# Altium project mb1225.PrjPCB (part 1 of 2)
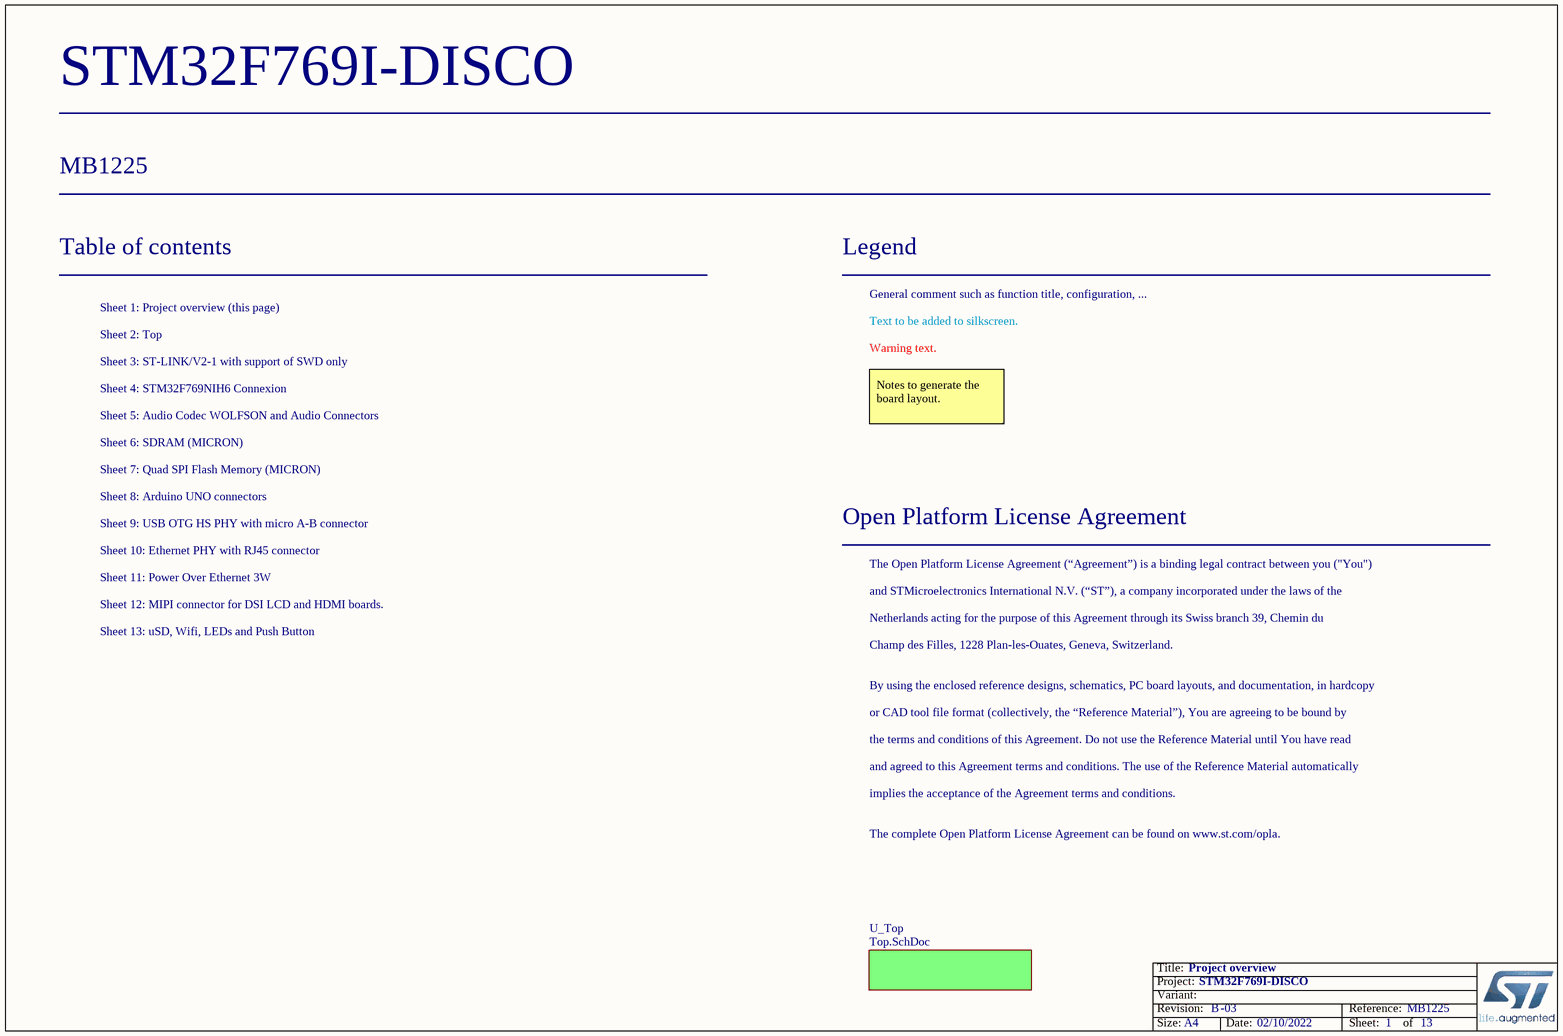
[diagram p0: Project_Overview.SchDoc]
Board_Reference: MB1225; Board_PCB_Revision: B; Board_Name: STM32F769I-DISCO; Board_document_Date: 02/10/2022; Board_Assembly_Revision: 03
13 sheets, 456 parts. Net scope: flat (ports and power ports of the same name join across sheets).
Board file: MB1225.PcbDoc
Sheets:
  Project_Overview.SchDoc
    U_Top = TOP.SchDoc
      U_ST_LINK_V2-1 = ST_LINK_V2-1.SCHDOC
      U_AUDIO = AUDIO.SchDoc
      U_Peripherals = Peripherals.SchDoc
      U_QSPI = QSPI.SchDoc
      U_Arduino_ Connectors = Arduino_ Connectors.SchDoc
      U_SDRAM = SDRAM.SchDoc
      U_USB_OTG_HS = USB_OTG_HS.SchDoc
      U_STM32F7 = STM32F7.SchDoc
      U_Ethernet = Ethernet.SchDoc
        U_PoE = PoE.SchDoc
      U_DSI_LCD = DSI_LCD.SchDoc

## Sheet Project_Overview.SchDoc: Project overview
size A4; Date: Not used; ApprovedBy: Not used; CheckedBy: Not used; Author: Not used; CompanyName: STMicroelectronics; DrawnBy: Not used; Engineer: Not used; Organization: Not used; Address1: Not used; Address2: Not used; Address3: Not used; Address4: Not used; DocumentNumber: Not used; Revision: Not used; SheetNumber: 1; SheetTotal: 13

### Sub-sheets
U_Top = Top.SchDoc: no entries

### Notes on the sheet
- Table of contents
- Sheet 1: Project overview (this page)
- Legend
- General comment such as function title, configuration, ...
- Sheet 2: Top
- Sheet 3: ST-LINK/V2-1 with support of SWD only
- Text to be added to silkscreen.
- Warning text.
- Sheet 4: STM32F769NIH6 Connexion
- Sheet 6: SDRAM (MICRON)
- Sheet 5: Audio Codec WOLFSON and Audio Connectors
- Notes to generate the board layout.
- Sheet 7: Quad SPI Flash Memory (MICRON)
- Sheet 8: Arduino UNO connectors
- Sheet 9: USB OTG HS PHY with micro A-B connector
- Sheet 10: Ethernet PHY with RJ45 connector
- Sheet 11: Power Over Ethernet 3W
- Open Platform License Agreement
- The Open Platform License Agreement (“Agreement”) is a binding legal contract between you ("You")
- Sheet 12: MIPI connector for DSI LCD and HDMI boards.
- Sheet 13: uSD, Wifi, LEDs and Push Button
- and STMicroelectronics International N.V. (“ST”), a company incorporated under the laws of the
- Netherlands acting for the purpose of this Agreement through its Swiss branch 39, Chemin du
- Champ des Filles, 1228 Plan-les-Ouates, Geneva, Switzerland.
- By using the enclosed reference designs, schematics, PC board layouts, and documentation, in hardcopy
- or CAD tool file format (collectively, the “Reference Material”), You are agreeing to be bound by
- the terms and conditions of this Agreement. Do not use the Reference Material until You have read
- and agreed to this Agreement terms and conditions. The use of the Reference Material automatically
- implies the acceptance of the Agreement terms and conditions.
- The complete Open Platform License Agreement can be found on www.st.com/opla.

## Sheet TOP.SchDoc: STM32F769 Discovery Interconnexion
size A4; Date: 29-OCT-2015; Author: A.B; CompanyName: STMicroelectronics; Organization: MCD/TOOLS/GNB; Address1: 12, Rue Jules HOROWITZ; Address2: 38019 Grenoble; Address3: FRANCE; DocumentNumber: MB1225; Revision: B-01; SheetNumber: 2; SheetTotal: 13; Project: STM32F769I-DISCO
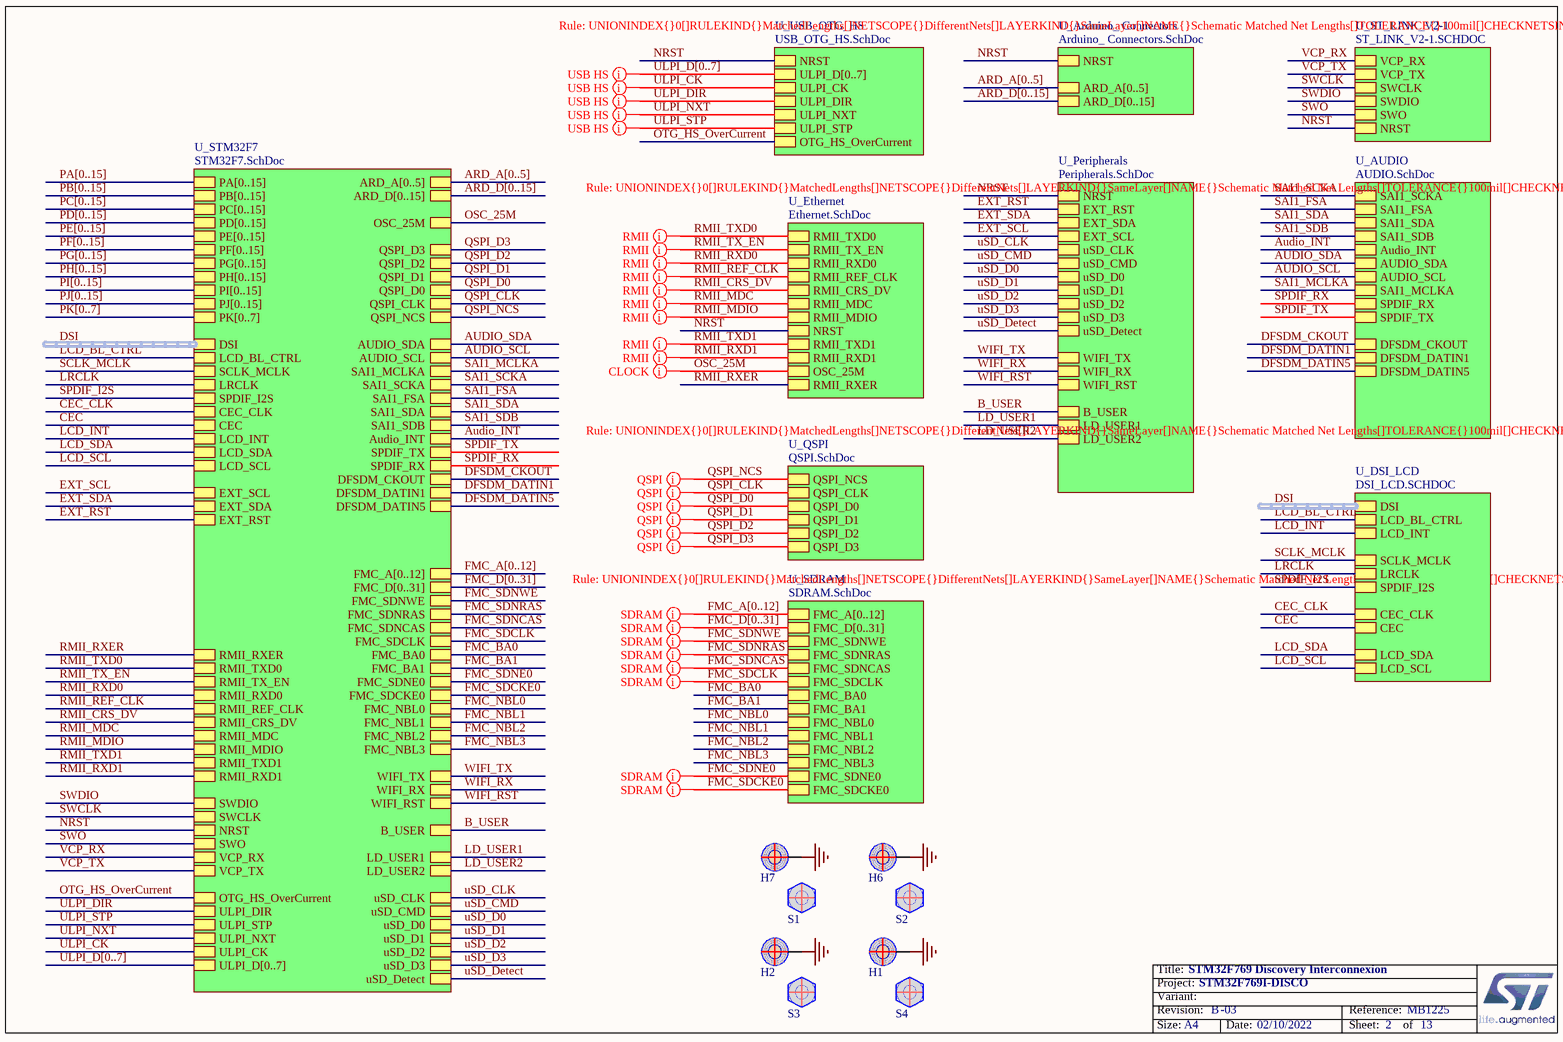
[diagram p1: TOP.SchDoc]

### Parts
H1  POSITION HOLE C6D3R5  [HOLE_C6D3R5]  (value not drawn)
H2  POSITION HOLE C6D3R5  [HOLE_C6D3R5]  (value not drawn)
H6  POSITION HOLE C6D3R5  [HOLE_C6D3R5]  (value not drawn)
H7  POSITION HOLE C6D3R5  [HOLE_C6D3R5]  (value not drawn)
S1  Nylon Screw/Spacer M3x12.7  (value not drawn)
S2  Nylon Screw/Spacer M3x12.7  (value not drawn)
S3  Nylon Screw/Spacer M3x12.7  (value not drawn)
S4  Nylon Screw/Spacer M3x12.7  (value not drawn)

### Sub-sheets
U_Arduino_ Connectors = Arduino_ Connectors.SchDoc: NRST, ARD_D[0..15], ARD_A[0..5]
U_AUDIO = AUDIO.SchDoc: AUDIO_SDA, AUDIO_SCL, SAI1_MCLKA, SPDIF_RX, SAI1_SCKA, SAI1_FSA, SAI1_SDA, SAI1_SDB, Audio_INT, SPDIF_TX, DFSDM_CKOUT, DFSDM_DATIN1, DFSDM_DATIN5
U_DSI_LCD = DSI_LCD.SCHDOC: DSI (harness DSI), LCD_INT, LCD_BL_CTRL, SCLK_MCLK, LRCLK, SPDIF_I2S, CEC_CLK, CEC, LCD_SDA, LCD_SCL
U_Ethernet = Ethernet.SchDoc: RMII_TXD0, RMII_TX_EN, RMII_RXD0, RMII_REF_CLK, RMII_CRS_DV, RMII_MDC, RMII_MDIO, NRST, RMII_TXD1, RMII_RXD1, OSC_25M, RMII_RXER
U_Peripherals = Peripherals.SchDoc: NRST, EXT_RST, EXT_SCL, EXT_SDA, uSD_CLK, uSD_CMD, uSD_D0, uSD_D1, uSD_D2, uSD_D3, uSD_Detect, B_USER, WIFI_TX, WIFI_RX, WIFI_RST, LD_USER1, LD_USER2
U_QSPI = QSPI.SchDoc: QSPI_D0, QSPI_D3, QSPI_D1, QSPI_CLK, QSPI_NCS, QSPI_D2
U_SDRAM = SDRAM.SchDoc: FMC_A[0..12], FMC_SDNWE, FMC_SDNRAS, FMC_SDNCAS, FMC_SDCLK, FMC_BA0, FMC_BA1, FMC_NBL0, FMC_NBL1, FMC_SDNE0, FMC_SDCKE0, FMC_D[0..31], FMC_NBL2, FMC_NBL3
U_ST_LINK_V2-1 = ST_LINK_V2-1.SCHDOC: SWDIO, SWCLK, NRST, VCP_RX, VCP_TX, SWO
U_STM32F7 = STM32F7.SchDoc: PA[0..15], PB[0..15], PC[0..15], PD[0..15], PE[0..15], PF[0..15], PG[0..15], PH[0..15], PI[0..15], PJ[0..15], PK[0..7], OSC_25M, RMII_TXD0, RMII_TX_EN, RMII_RXD0, RMII_REF_CLK, RMII_CRS_DV, RMII_MDC, RMII_MDIO, RMII_TXD1, RMII_RXD1, ULPI_D[0..7], ULPI_CK, ULPI_DIR, ULPI_NXT, ULPI_STP, QSPI_D0, QSPI_D3, QSPI_D1, QSPI_CLK, QSPI_NCS, AUDIO_SDA, AUDIO_SCL, SAI1_MCLKA, EXT_SCL, EXT_SDA, EXT_RST, uSD_CLK, uSD_CMD, uSD_D0, uSD_D1, uSD_D2, uSD_D3, uSD_Detect, SWDIO, SWCLK, NRST, SWO, VCP_RX, VCP_TX, FMC_A[0..12], FMC_D[0..31], FMC_SDNWE, FMC_SDNRAS, FMC_SDNCAS, FMC_SDCLK, FMC_BA0, FMC_BA1, FMC_SDNE0, FMC_SDCKE0, FMC_NBL0, FMC_NBL1, SPDIF_RX, QSPI_D2, B_USER, ARD_D[0..15], RMII_RXER, OTG_HS_OverCurrent, SAI1_SCKA, SAI1_FSA, SAI1_SDA, SAI1_SDB, Audio_INT, SPDIF_TX, FMC_NBL2, FMC_NBL3, DSI (harness DSI), LCD_BL_CTRL, SCLK_MCLK, LRCLK, SPDIF_I2S, CEC_CLK, CEC, LCD_INT, LCD_SDA, LCD_SCL, WIFI_RST, WIFI_RX, WIFI_TX, ARD_A[0..5], LD_USER1, LD_USER2, DFSDM_CKOUT, DFSDM_DATIN1, DFSDM_DATIN5
U_USB_OTG_HS = USB_OTG_HS.SchDoc: ULPI_D[0..7], ULPI_CK, ULPI_DIR, ULPI_NXT, ULPI_STP, NRST, OTG_HS_OverCurrent

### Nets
GND: H1.1 H2.1 H6.1 H7.1  [project net POE7]
Audio_INT: sheet U_AUDIO/Audio_INT, sheet U_STM32F7/Audio_INT
AUDIO_SCL: sheet U_AUDIO/AUDIO_SCL, sheet U_STM32F7/AUDIO_SCL
AUDIO_SDA: sheet U_AUDIO/AUDIO_SDA, sheet U_STM32F7/AUDIO_SDA
B_USER: sheet U_Peripherals/B_USER, sheet U_STM32F7/B_USER
CEC: sheet U_STM32F7/CEC, sheet U_DSI_LCD/CEC
CEC_CLK: sheet U_STM32F7/CEC_CLK, sheet U_DSI_LCD/CEC_CLK
DFSDM_CKOUT: sheet U_AUDIO/DFSDM_CKOUT, sheet U_STM32F7/DFSDM_CKOUT
DFSDM_DATIN1: sheet U_AUDIO/DFSDM_DATIN1, sheet U_STM32F7/DFSDM_DATIN1
DFSDM_DATIN5: sheet U_AUDIO/DFSDM_DATIN5, sheet U_STM32F7/DFSDM_DATIN5
EXT_RST: sheet U_Peripherals/EXT_RST, sheet U_STM32F7/EXT_RST
EXT_SCL: sheet U_Peripherals/EXT_SCL, sheet U_STM32F7/EXT_SCL
EXT_SDA: sheet U_Peripherals/EXT_SDA, sheet U_STM32F7/EXT_SDA
FMC_BA0: sheet U_SDRAM/FMC_BA0, sheet U_STM32F7/FMC_BA0
FMC_BA1: sheet U_SDRAM/FMC_BA1, sheet U_STM32F7/FMC_BA1
FMC_NBL0: sheet U_SDRAM/FMC_NBL0, sheet U_STM32F7/FMC_NBL0
FMC_NBL1: sheet U_SDRAM/FMC_NBL1, sheet U_STM32F7/FMC_NBL1
FMC_NBL2: sheet U_SDRAM/FMC_NBL2, sheet U_STM32F7/FMC_NBL2
FMC_NBL3: sheet U_SDRAM/FMC_NBL3, sheet U_STM32F7/FMC_NBL3
FMC_SDCKE0: sheet U_SDRAM/FMC_SDCKE0, sheet U_STM32F7/FMC_SDCKE0
FMC_SDCLK: sheet U_SDRAM/FMC_SDCLK, sheet U_STM32F7/FMC_SDCLK
FMC_SDNCAS: sheet U_SDRAM/FMC_SDNCAS, sheet U_STM32F7/FMC_SDNCAS
FMC_SDNE0: sheet U_SDRAM/FMC_SDNE0, sheet U_STM32F7/FMC_SDNE0
FMC_SDNRAS: sheet U_SDRAM/FMC_SDNRAS, sheet U_STM32F7/FMC_SDNRAS
FMC_SDNWE: sheet U_SDRAM/FMC_SDNWE, sheet U_STM32F7/FMC_SDNWE
LCD_BL_CTRL: sheet U_STM32F7/LCD_BL_CTRL, sheet U_DSI_LCD/LCD_BL_CTRL
LCD_INT: sheet U_STM32F7/LCD_INT, sheet U_DSI_LCD/LCD_INT
LCD_SCL: sheet U_STM32F7/LCD_SCL, sheet U_DSI_LCD/LCD_SCL
LCD_SDA: sheet U_STM32F7/LCD_SDA, sheet U_DSI_LCD/LCD_SDA
LD_USER1: sheet U_Peripherals/LD_USER1, sheet U_STM32F7/LD_USER1
LD_USER2: sheet U_Peripherals/LD_USER2, sheet U_STM32F7/LD_USER2
LRCLK: sheet U_STM32F7/LRCLK, sheet U_DSI_LCD/LRCLK
NRST: sheet U_ST_LINK_V2-1/NRST, sheet U_Peripherals/NRST, sheet U_Arduino_ Connectors/NRST, sheet U_USB_OTG_HS/NRST, sheet U_STM32F7/NRST, sheet U_Ethernet/NRST
OSC_25M: sheet U_STM32F7/OSC_25M, sheet U_Ethernet/OSC_25M
OTG_HS_OverCurrent: sheet U_USB_OTG_HS/OTG_HS_OverCurrent, sheet U_STM32F7/OTG_HS_OverCurrent
QSPI_CLK: sheet U_QSPI/QSPI_CLK, sheet U_STM32F7/QSPI_CLK
QSPI_D0: sheet U_QSPI/QSPI_D0, sheet U_STM32F7/QSPI_D0
QSPI_D1: sheet U_QSPI/QSPI_D1, sheet U_STM32F7/QSPI_D1
QSPI_D2: sheet U_QSPI/QSPI_D2, sheet U_STM32F7/QSPI_D2
QSPI_D3: sheet U_QSPI/QSPI_D3, sheet U_STM32F7/QSPI_D3
QSPI_NCS: sheet U_QSPI/QSPI_NCS, sheet U_STM32F7/QSPI_NCS
RMII_CRS_DV: sheet U_STM32F7/RMII_CRS_DV, sheet U_Ethernet/RMII_CRS_DV
RMII_MDC: sheet U_STM32F7/RMII_MDC, sheet U_Ethernet/RMII_MDC
RMII_MDIO: sheet U_STM32F7/RMII_MDIO, sheet U_Ethernet/RMII_MDIO
RMII_REF_CLK: sheet U_STM32F7/RMII_REF_CLK, sheet U_Ethernet/RMII_REF_CLK
RMII_RXD0: sheet U_STM32F7/RMII_RXD0, sheet U_Ethernet/RMII_RXD0
RMII_RXD1: sheet U_STM32F7/RMII_RXD1, sheet U_Ethernet/RMII_RXD1
RMII_RXER: sheet U_STM32F7/RMII_RXER, sheet U_Ethernet/RMII_RXER
RMII_TX_EN: sheet U_STM32F7/RMII_TX_EN, sheet U_Ethernet/RMII_TX_EN
RMII_TXD0: sheet U_STM32F7/RMII_TXD0, sheet U_Ethernet/RMII_TXD0
RMII_TXD1: sheet U_STM32F7/RMII_TXD1, sheet U_Ethernet/RMII_TXD1
SAI1_FSA: sheet U_AUDIO/SAI1_FSA, sheet U_STM32F7/SAI1_FSA
SAI1_MCLKA: sheet U_AUDIO/SAI1_MCLKA, sheet U_STM32F7/SAI1_MCLKA
SAI1_SCKA: sheet U_AUDIO/SAI1_SCKA, sheet U_STM32F7/SAI1_SCKA
SAI1_SDA: sheet U_AUDIO/SAI1_SDA, sheet U_STM32F7/SAI1_SDA
SAI1_SDB: sheet U_AUDIO/SAI1_SDB, sheet U_STM32F7/SAI1_SDB
SCLK_MCLK: sheet U_STM32F7/SCLK_MCLK, sheet U_DSI_LCD/SCLK_MCLK
SPDIF_I2S: sheet U_STM32F7/SPDIF_I2S, sheet U_DSI_LCD/SPDIF_I2S
SPDIF_RX: sheet U_AUDIO/SPDIF_RX, sheet U_STM32F7/SPDIF_RX
SPDIF_TX: sheet U_AUDIO/SPDIF_TX, sheet U_STM32F7/SPDIF_TX
SWCLK: sheet U_ST_LINK_V2-1/SWCLK, sheet U_STM32F7/SWCLK
SWDIO: sheet U_ST_LINK_V2-1/SWDIO, sheet U_STM32F7/SWDIO
SWO: sheet U_ST_LINK_V2-1/SWO, sheet U_STM32F7/SWO
ULPI_CK: sheet U_USB_OTG_HS/ULPI_CK, sheet U_STM32F7/ULPI_CK
ULPI_DIR: sheet U_USB_OTG_HS/ULPI_DIR, sheet U_STM32F7/ULPI_DIR
ULPI_NXT: sheet U_USB_OTG_HS/ULPI_NXT, sheet U_STM32F7/ULPI_NXT
ULPI_STP: sheet U_USB_OTG_HS/ULPI_STP, sheet U_STM32F7/ULPI_STP
uSD_CLK: sheet U_Peripherals/uSD_CLK, sheet U_STM32F7/uSD_CLK
uSD_CMD: sheet U_Peripherals/uSD_CMD, sheet U_STM32F7/uSD_CMD
uSD_D0: sheet U_Peripherals/uSD_D0, sheet U_STM32F7/uSD_D0
uSD_D1: sheet U_Peripherals/uSD_D1, sheet U_STM32F7/uSD_D1
uSD_D2: sheet U_Peripherals/uSD_D2, sheet U_STM32F7/uSD_D2
uSD_D3: sheet U_Peripherals/uSD_D3, sheet U_STM32F7/uSD_D3
uSD_Detect: sheet U_Peripherals/uSD_Detect, sheet U_STM32F7/uSD_Detect
VCP_RX: sheet U_ST_LINK_V2-1/VCP_RX, sheet U_STM32F7/VCP_RX
VCP_TX: sheet U_ST_LINK_V2-1/VCP_TX, sheet U_STM32F7/VCP_TX
WIFI_RST: sheet U_Peripherals/WIFI_RST, sheet U_STM32F7/WIFI_RST
WIFI_RX: sheet U_Peripherals/WIFI_RX, sheet U_STM32F7/WIFI_RX
WIFI_TX: sheet U_Peripherals/WIFI_TX, sheet U_STM32F7/WIFI_TX

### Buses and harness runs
bus ARD_A[0..5] = sheet U_Arduino_ Connectors/ARD_A[0..5]
bus ARD_A[0..5] = sheet U_STM32F7/ARD_A[0..5]
bus ARD_D[0..15] = sheet U_Arduino_ Connectors/ARD_D[0..15]
bus ARD_D[0..15] = sheet U_STM32F7/ARD_D[0..15]
bus FMC_A[0..12] = sheet U_SDRAM/FMC_A[0..12]
bus FMC_A[0..12] = sheet U_STM32F7/FMC_A[0..12]
bus FMC_D[0..31] = sheet U_SDRAM/FMC_D[0..31]
bus FMC_D[0..31] = sheet U_STM32F7/FMC_D[0..31]
bus PA[0..15] = sheet U_STM32F7/PA[0..15]
bus PB[0..15] = sheet U_STM32F7/PB[0..15]
bus PC[0..15] = sheet U_STM32F7/PC[0..15]
bus PD[0..15] = sheet U_STM32F7/PD[0..15]
bus PE[0..15] = sheet U_STM32F7/PE[0..15]
bus PF[0..15] = sheet U_STM32F7/PF[0..15]
bus PG[0..15] = sheet U_STM32F7/PG[0..15]
bus PH[0..15] = sheet U_STM32F7/PH[0..15]
bus PI[0..15] = sheet U_STM32F7/PI[0..15]
bus PJ[0..15] = sheet U_STM32F7/PJ[0..15]
bus PK[0..7] = sheet U_STM32F7/PK[0..7]
bus ULPI_D[0..7] = sheet U_STM32F7/ULPI_D[0..7]
bus ULPI_D[0..7] = sheet U_USB_OTG_HS/ULPI_D[0..7]
harness DSI = sheet U_DSI_LCD/DSI
harness DSI = sheet U_STM32F7/DSI

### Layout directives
rule Matched Net Lengths [Tolerance = 100mil]: (no net found under the mark), FMC_SDCKE0, FMC_SDCLK, FMC_SDNCAS, FMC_SDNE0, FMC_SDNRAS, FMC_SDNWE, QSPI_CLK, QSPI_D0, QSPI_D1, QSPI_D2, QSPI_D3, QSPI_NCS, RMII_CRS_DV, RMII_MDC, RMII_MDIO, RMII_REF_CLK, RMII_RXD0, RMII_RXD1, RMII_TX_EN, RMII_TXD0, RMII_TXD1, ULPI_CK, ULPI_DIR, ULPI_NXT, ULPI_STP
rule Undefined: OSC_25M

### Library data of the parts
S1-S4 = Nylon_ScrewM3_Spacer_12.7: Nylon Screw M3 and Spacer 12.7; Manuf_Part_1: Screw M3x6 / Spacer M3x12.7; Manuf_1: JIUBABA; Provided: Sub Co

## Sheet ST_LINK_V2-1.SCHDOC: ST-LINK/V2-1 with support of SWD only
size A4; Date: 29-OCT-2015; Author: A.B; CompanyName: STMicroelectronics; Organization: MCD/TOOLS/GNB; Address1: 12, Rue Jules HOROWITZ; Address2: 38019 Grenoble; Address3: FRANCE; DocumentNumber: MB1225; Revision: B-01; SheetNumber: 3; SheetTotal: 13; Project: STM32F769I-DISCO
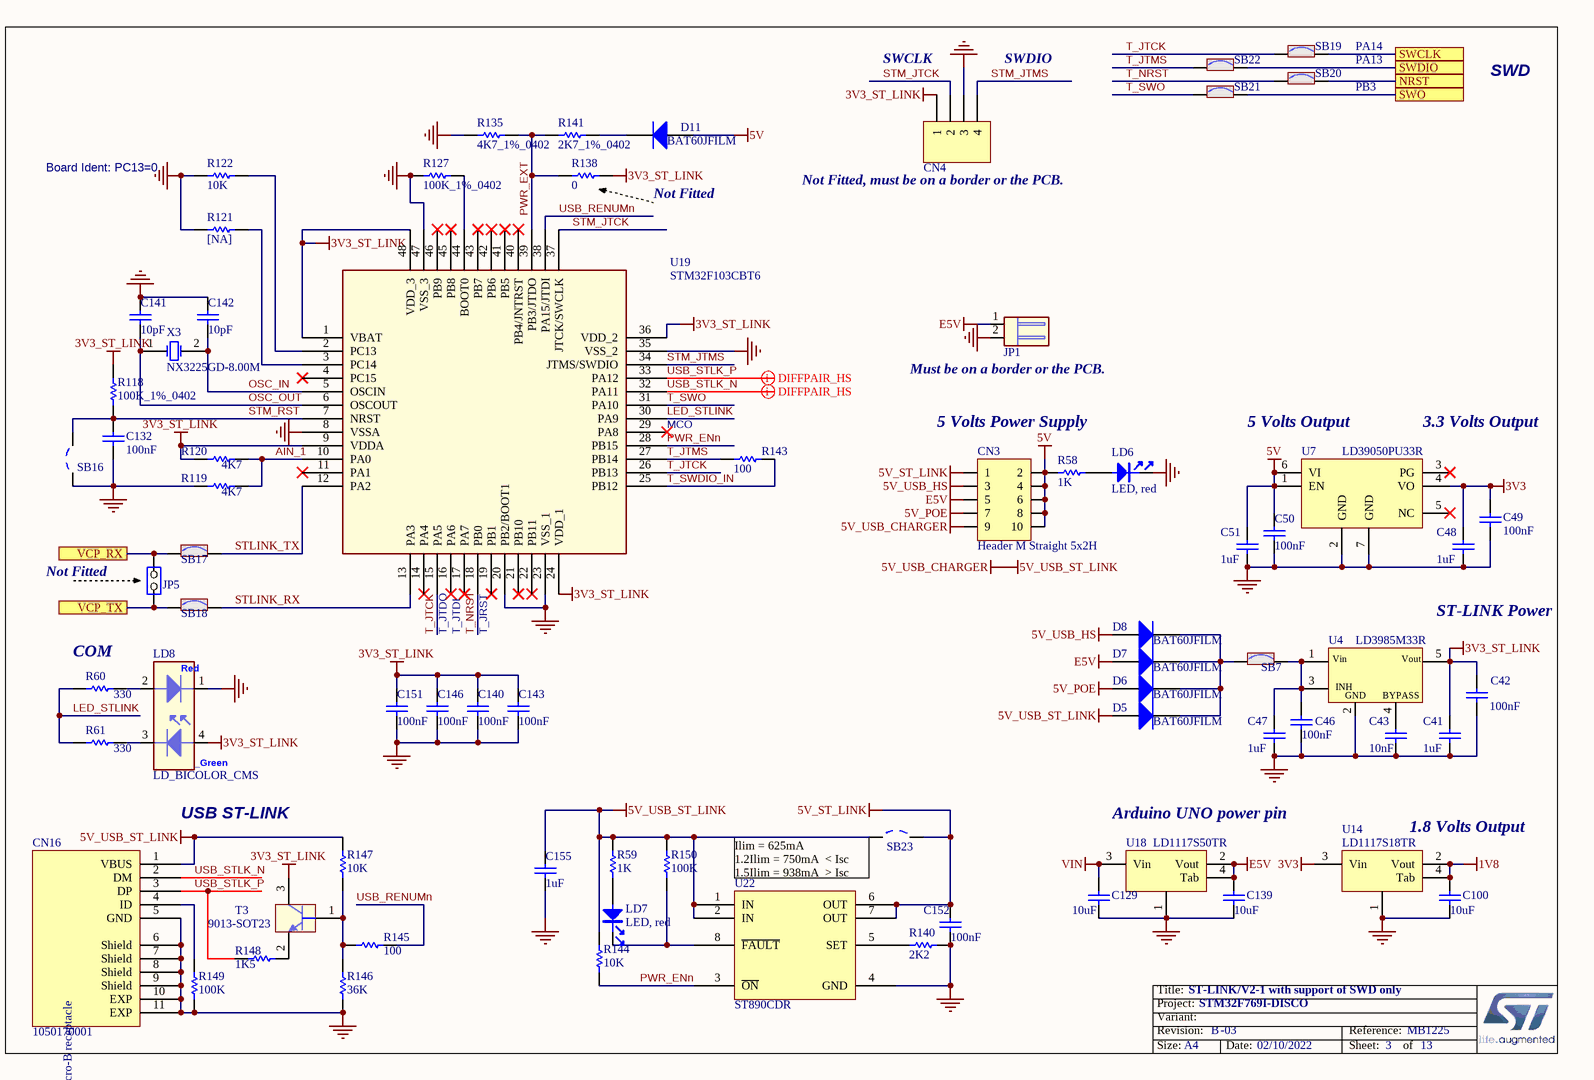
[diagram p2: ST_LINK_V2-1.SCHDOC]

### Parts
C41  1uF  [0603C]
C42  100nF  [0402C]
C43  10nF  [0603C]
C46  100nF  [0402C]
C47  1uF  [0603C]
C48  1uF  [0603C]
C49  100nF  [0402C]
C50  100nF  [0402C]
C51  1uF  [0603C]
C100  10uF  [0603C]
C129  10uF  [0805C]
C132  100nF  [0402C]
C139  10uF  [0805C]
C140  100nF  [0402C]
C141  10pF  [0402C]
C142  10pF  [0402C]
C143  100nF  [0402C]
C146  100nF  [0402C]
C151  100nF  [0402C]
C152  100nF  [0402C]
C155  1uF  [0603C]
CN3  Header M Straight 5x2H  [HDR_2X5_2R54]
CN4  Header 4  [HDR_1X4_2R54]  (value not drawn)
CN16  1050170001  [MICRO_USB_B_105017]
D5  BAT60JFILM  [SOD-323]
D6  BAT60JFILM  [SOD-323]
D7  BAT60JFILM  [SOD-323]
D8  BAT60JFILM  [SOD-323]
D11  BAT60JFILM  [SOD-323]
JP1  WF25402-06421  [HDR_1X2_2R54_RA_11R35]  (value not drawn)
JP5  JP2  [SIP2]  (value not drawn)
LD6  LED, red  [0603D]
LD7  LED, red  [0603D]
LD8  LD_BICOLOR_CMS  [LED2_3528]
R58  1K  [0402R]
R59  1K  [0402R]
R60  330  [0402R]
R61  330  [0402R]
R118  100K_1%_0402  [0402R]
R119  4K7  [0402R]
R120  4K7  [0402R]
R121  [NA]  [0402R]
R122  10K  [0402R]
R127  100K_1%_0402  [0402R]
R135  4K7_1%_0402  [0402R]
R138  0  [0402R]
R140  2K2  [0402R]
R141  2K7_1%_0402  [0402R]
R143  100  [0402R]
R144  10K  [0402R]
R145  100  [0402R]
R146  36K  [0402R]
R147  10K  [0402R]
R148  1K5  [0402R]
R149  100K  [0402R]
R150  100K  [0402R]
SB7  Solder Bridge ON  [JP2_SMD]  (value not drawn)
SB16  Solder Bridge OFF  [JP2_SMD]  (value not drawn)
SB17  Solder Bridge ON  [JP2_SMD]  (value not drawn)
SB18  Solder Bridge ON  [JP2_SMD]  (value not drawn)
SB19  Solder Bridge ON  [JP2_SMD]  (value not drawn)
SB20  Solder Bridge ON  [JP2_SMD]  (value not drawn)
SB21  Solder Bridge ON  [JP2_SMD]  (value not drawn)
SB22  Solder Bridge ON  [JP2_SMD]  (value not drawn)
SB23  Solder Bridge OFF  [JP2_SMD]  (value not drawn)
T3  9013-SOT23  [SOT-23]
U4  LD3985M33R  [SOT-23-5L]
U7  LD39050PU33R  [DFN6_0R95_3X3]
U14  LD1117S18TR  [SOT-223]
U18  LD1117S50TR  [SOT-223]
U19  STM32F103CBT6  [LQFP48_0R5_9X9]
U22  ST890CDR  [SOIC8_1R27_4R9X6]
X3  NX3225GD-8.00M  [XTAL_2SM_3R2X2R5_H1]

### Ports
NRST, SWCLK, SWDIO, SWO, VCP_RX, VCP_TX

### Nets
1V8: C100.2 U14.2(Vout) U14.4(Tab)
3V3: C48.2 C49.2 U7.4(VO) U14.3(Vin)
3V3_ST_LINK: C41.1 C42.2 C140.1 C143.2 C146.2 C151.2 CN4.1 LD8.4 R118.2 R120.1 R138.2 T3.3(C) U4.5(Vout) U19.1(VBAT) U19.9(VDDA) U19.24(VDD_1) U19.36(VDD_2) U19.48(VDD_3)
5V: C50.2 C51.2 CN3.2 CN3.4 CN3.6 CN3.8 CN3.10 D11.1(A) R58.1 U7.1(EN) U7.6(VI)
5V_POE: CN3.7 D6.1(A)
5V_ST_LINK: C152.2 CN3.1 SB23.2 U22.6(OUT) U22.7(OUT)
5V_USB_CHARGER: C155.2 CN3.9 CN16.1(VBUS) D5.1(A) R59.2 R144.2 R147.2 R150.2 SB23.1 U22.1(IN) U22.2(IN)  [also labelled 5V_USB_ST_LINK]
5V_USB_HS: CN3.3 D8.1(A)
E5V: C139.2 CN3.5 D7.1(A) JP1.1 U18.2(Vout) U18.4(Tab)
GND: C41.2 C42.1 C43.1 C46.1 C47.1 C48.1 C49.1 C50.1 C51.1 C100.1 C129.1 C132.1 C139.1 C140.2 C141.1 C142.1 C143.1 C146.1 C151.1 C152.1 C155.1 CN4.3 CN16.5(GND) CN16.6(Shield) CN16.7(Shield) CN16.8(Shield) CN16.9(Shield) CN16.10(EXP) CN16.11(EXP) JP1.2 LD6.2 LD8.1 R119.1 R121.1 R122.1 R127.1 R135.1 R140.2 R146.1 R149.1 SB16.1 U4.2(GND) U7.2(GND) U7.7(GND) U14.1 U18.1 U19.8(VSSA) U19.20(PB2/BOOT1) U19.23(VSS_1) U19.35(VSS_2) U19.47(VSS_3) U22.4(GND)  [project net POE7]
VIN: C129.2 U18.3(Vin)
AIN_1: R119.2 R120.2 U19.10(PA0)
LED_STLINK: R60.1 R61.1 U19.30(PA9)
NRST: SB20.2 ; port NRST
OSC_IN: C142.2 U19.5(OSCIN) X3.2(OSC2)
OSC_OUT: C141.2 U19.6(OSCOUT) X3.1(OSC1)
PA9: JP5.1(COMMON) SB18.1 ; port VCP_TX
PA10: JP5.2(NO) SB17.1 ; port VCP_RX
PA13: SB22.2 ; port SWDIO
PA14: SB19.2 ; port SWCLK
PWR_ENn: R144.1 U19.28(PB15) U22.3(~{ON})
PWR_EXT: R135.2 R138.1 R141.1 U19.39(PB3/JTDO)
STLINK_RX: SB18.2 U19.13(PA3)
STLINK_TX: SB17.2 U19.12(PA2)
STM_JTCK: CN4.2 U19.37(JTCK/SWCLK)
STM_JTMS: CN4.4 U19.34(JTMS/SWDIO)
STM_RST: C132.2 R118.1 SB16.2 U19.7(NRST)
SWO: SB21.2 ; port SWO
T_JTCK: SB19.1 U19.15(PA5) U19.26(PB13)
T_JTMS: R143.1 SB22.1 U19.27(PB14)
T_NRST: SB20.1 U19.18(PB0)
T_SWDIO_IN: R143.2 U19.25(PB12)
T_SWO: SB21.1 U19.31(PA10)
USB_RENUMn: R145.2 U19.38(PA15/JTDI)
USB_STLK_N: CN16.2(DM) U19.32(PA11)
USB_STLK_P: CN16.3(DP) R148.1 U19.33(PA12)
NetC43_2: C43.2 U4.4(BYPASS)
NetC46_2: C46.2 C47.2 SB7.2 U4.1(Vin) U4.3(CE)
NetCN16_4: CN16.4(ID) R149.2
NetD5_2: D5.2(K) D6.2(K) D7.2(K) D8.2(K) SB7.1
NetD11_2: D11.2(K) R141.2
NetLD6_1: LD6.1 R58.2
NetLD7_1: LD7.1 R59.1
NetLD7_2: LD7.2 R150.1 U22.8(~{FAULT})
NetLD8_2: LD8.2 R60.2
NetLD8_3: LD8.3 R61.2
NetR121_2: R121.2 U19.3(PC14)
NetR122_2: R122.2 U19.2(PC13)
NetR127_2: R127.2 U19.44(BOOT0)
NetR140_1: R140.1 U22.5(SET)
NetR145_1: R145.1 R146.2 R147.1 T3.1(B)
NetR148_2: R148.2 T3.2(E)

Not connected (* = marked no-connect by the designer): U7 3(PG)* 5(NC)*; U19 4(PC15)* 11(PA1)* 14(PA4)* 16(PA6)* 17(PA7)* 19(PB1)* 21(PB10)* 22(PB11)* 29(PA8)* 40(PB4/JNTRST)* 41(PB5)* 42(PB6)* 43(PB7)* 45(PB8)* 46(PB9)*

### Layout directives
differential pair: USB_STLK_N, USB_STLK_P

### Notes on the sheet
- SWCLK
- SWDIO
- PA14
- PA13
- PB3
- SWD
- Board Ident: PC13=0
- Not Fitted
- (near CN4) Not Fitted, must be on a border or the PCB.
- (near JP1) Must be on a border or the PCB.
- MCO
- 5 Volts Power Supply
- (near U7) 5 Volts Output
- (near U7) 3.3 Volts Output
- (near JP5) Not Fitted
- (near R60) COM
- T_JTDO
- T_JTDI
- T_JRST
- ST-LINK Power
- USB ST-LINK
- (near SB23) Ilim = 625mA
  1.2Ilim = 750mA  < Isc
  1.5Ilim = 938mA  > Isc
- Arduino UNO power pin
- (near U14) 1.8 Volts Output

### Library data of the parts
C41 C47 C48 C51 C155 = Cap_1uF_X5R_10%_0603: Capacitor,1uF,16V,X5R,10%,0603,YAGEO; Manuf_Part_1: CC0603KRX5R7BB105
C42 C46 C49 C50 C132 C140 C143 C146 C151 C152 = Cap_100nF_X7R_10%_0402: Capacitor,100nF,16V,X7R,10%,0402,YAGEO; Manuf_Part_1: CC0402KRX7R7BB104
C43 = Cap_10nF_X7R_10%_0603: Capacitor,10nF,50V,X7R,10%,0603,YAGEO; Manuf_Part_1: CC0603KRX7R9BB103
C100 = Cap_10uF_X5R_10%_0603: Capacitor,10uF,6.3V,X5R,10%,0603,YAGEO; Manuf_Part_1: CC0603KRX5R5BB106
C129 C139 = Cap_10uF_X5R_10%_0805: Capacitor,10uF,25V,X5R,10%,0805,YAGEO; Manuf_Part_1: CC0805KRX5R8BB106
C141 C142 = Cap_10pF_NPO_5%_0402: Capacitor,10pF,50V,NPO,5%,0402,YAGEO; Order: CC0402JRNPO9BN100
CN3 = Header 5X2M: Header Male, 5-Pin, Dual row, Straight, AMD; Manuf_Part_1: 826632-5
CN4 = Header 4: Header, 4-Pin; Fitted: NO
CN16 = 1050170001: USB-MICRO-B, 1050170001, SMT, MOLEX
D5-D8 D11 = BAT60JFILM: Manuf_1: STM; Provided: ST; ECCN_US/EU: EAR99/NEC; Ref St: 9151097
JP1 = JP2_RA: Header, 2-Pins, Single row, Right Angle, 2.54 mm pitch, DIP; Manuf_1: ATOM
JP5 = JP2: Fitted: NO
LD6 LD7 = LED_red: LED, red, 0603; Manuf_1: everlight; Manuf_Part_1: 19-213-R6C-AP1Q2B/3T; ECCN_US/EU: EAR99/NEC
LD8 = LD_BICOLOR_CMS: Bicolor Led; Manuf_Part_1: HSMF-A201-A00J1; Manuf_1: Avago Technologies; Manuf_2: everluck; Manuf_Part_2: LE-RGW35280; Ref St: xxxxxx; ECCN_US/EU: EAR99/NEC
R58 R59 = Res_1K_1%_0402: Resistor,1K,0402,1%,YAGEO; Manuf_Part_1: RC0402FR-071KL
R60 R61 = Res_330_1%_0402: Resistor,330,0402,1%,YAGEO; Manuf_Part_1: RC0402FR-07330RL
R118 R127 R149 R150 = Res_100K_1%_0402: Resistor,100K,0402,1%,YAGEO; Manuf_Part_1: RC0402FR-07100KL; Manuf_Part_2: RT0402FRE07100KL
R119 R120 R135 = Res_4K7_1%_0402: Resistor,4K7,0402,1%,YAGEO; Manuf_Part_1: RC0402FR-074K7L; Manuf_Part_2: RT0402FRE074K7L
R121 = Res_NA_0402: Resistor,[NA],0402; Fitted: NO
R122 R144 R147 = Res_10K_1%_0402: Resistor,10K,0402,1%,YAGEO; Manuf_Part_1: RC0402FR-0710KL
R138 = Res_0_5%_0402: Resistor,0,0402,5%,YAGEO; Manuf_Part_1: RC0402JR-070RL; Order: 2363467; Fitted: NO
R140 = Res_2K2_1%_0402: Resistor,2K2,0402,1%,YAGEO; Manuf_Part_1: RC0402FR-072K2L
R141 = Res_2K7_1%_0402: Resistor,2K7,0402,1%,YAGEO; Manuf_Part_1: RC0402FR-072K7L
R143 R145 = Res_100_1%_0402: Resistor,100,0402,1%,YAGEO; Manuf_Part_1: RC0402FR-07100RL; Order: 9239111
R146 = Res_36K_1%_0402: Resistor,36K,0402,1%,YAGEO; Manuf_Part_1: RC0402FR-0736KL
R148 = Res_1K5_1%_0402: Resistor,1K5,0402,1%,YAGEO; Manuf_Part_1: RC0402FR-071K5L
SB7 SB17-SB22 = SB_ON: Solder: YES
SB16 SB23 = SB_OFF: Solder: NO
T3 = 9013-SOT23: NPN Bipolar Transistor; Manuf_1: NXP; Manuf_Part_1: BSR14; Order: 1081310; ECCN_US/EU: EAR99/NEC
U4 = LD3985M33R: Ultra low drop-low noise BiCMOS voltage, regulators low ESR capacitors compatible; Manuf_1: STM; Provided: ST; Ref St: 9176161; ECCN_US/EU: EAR99/NEC
U7 = LD39050P: Ultra low drop-low , 500 mA low quiescent current; Manuf_1: STM; Provided: ST; ECCN_US/EU: EAR99/NEC; Ref St: xxxxxxxx
U14 = LD1117S18TR: LOW DROP FIXED AND ADJUSTABLE POSITIVE VOLTAGE REGULATORS (1.8 Volts); Manuf_1: STM; Ref St: 9176180; ECCN_US/EU: EAR99/NEC; Provided: ST
U18 = LD1117S50TR: IC REG LDO 5V 0.8A SOT223; Manuf_1: STM; Ordered by: ST; ECCN_US/EU: EAR99/NEC; Ref St: 9176133
U19 = STM32F103CBT6: Medium-density performance line ARM-based 32-bit MCU with 128KB Flash; Manuf_1: STM; Ref St: xxxxxxxx; Provided: ST; ECCN_US/EU: 3A991A2/NEC
U22 = ST890CDR: 1.2 A current limited high-side power switch with thermal shutdown; Manuf_1: STM; ECCN_US/EU: EAR99/NEC; Provided: ST
X3 = XTAL_8M_NX3225GD: Crystal 8Mhz, 8pF, -+50PPM, SMD; Manuf_1: NDK; Manuf_Part_1: NX3225GD 8MHz EXS00A-CG04874; Manuf_Part_2: NX3225GD-8.000M-STD-CRA-3; ECCN_US/EU: EAR99/NEC; NDK Ref: X3127326; Ref St: 9157029; Provided: ST

## Sheet AUDIO.SchDoc: Audio Codec WOLFSON and Audio Connectors
size A4; Date: 29-OCT-2015; Author: A.B; CompanyName: STMicroelectronics; Organization: MCD/TOOLS/GNB; Address1: 12, Rue Jules HOROWITZ; Address2: 38019 Grenoble; Address3: FRANCE; DocumentNumber: MB1225; Revision: B-01; SheetNumber: 5; SheetTotal: 13; Project: STM32F769I-DISCO
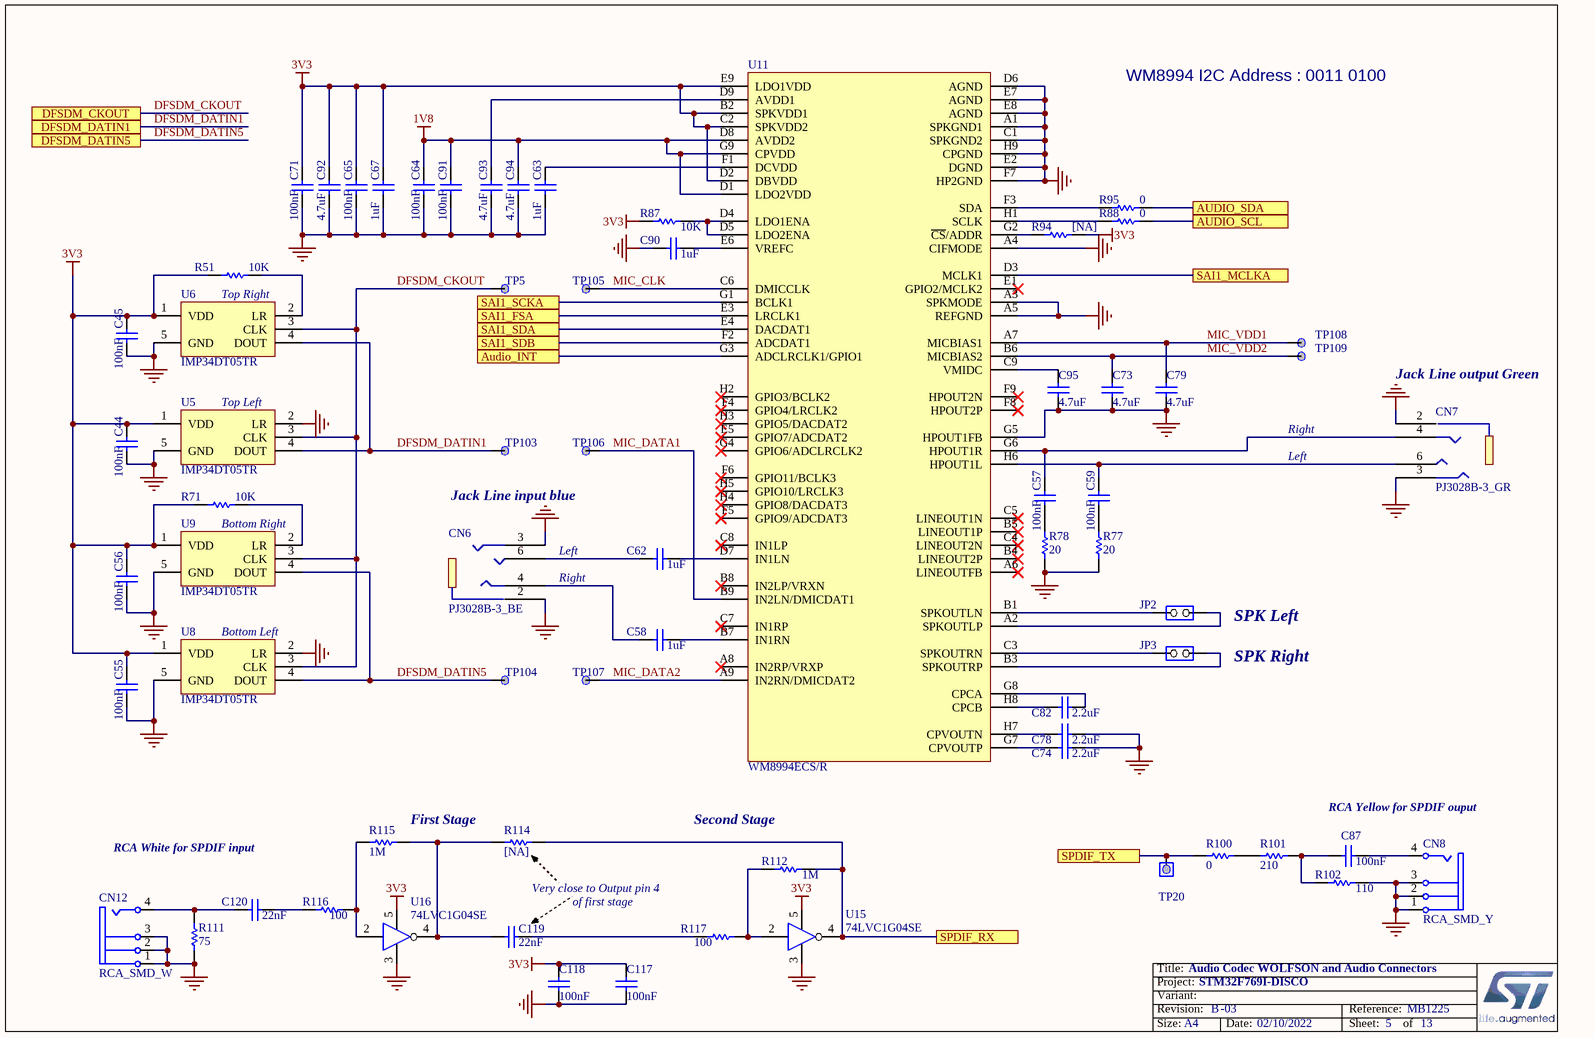
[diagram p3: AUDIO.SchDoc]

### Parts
C44  100nF  [0402C]
C45  100nF  [0402C]
C55  100nF  [0402C]
C56  100nF  [0402C]
C57  100nF  [0402C]
C58  1uF  [0603C]
C59  100nF  [0402C]
C62  1uF  [0603C]
C63  1uF  [0603C]
C64  100nF  [0402C]
C65  100nF  [0402C]
C67  1uF  [0603C]
C71  100nF  [0402C]
C73  4.7uF  [0603C]
C74  2.2uF  [0603C]
C78  2.2uF  [0603C]
C79  4.7uF  [0603C]
C82  2.2uF  [0603C]
C87  100nF  [0402C]
C90  1uF  [0603C]
C91  100nF  [0402C]
C92  4.7uF  [0603C]
C93  4.7uF  [0603C]
C94  4.7uF  [0603C]
C95  4.7uF  [0603C]
C117  100nF  [0402C]
C118  100nF  [0402C]
C119  22nF  [0402C]
C120  22nF  [0402C]
CN6  PJ3028B-3_BE  [PJ3028B]
CN7  PJ3028B-3_GR  [PJ3028B]
CN8  RCA_SMD_Y  [PHONE_JACK_JBB0819100002]
CN12  RCA_SMD_W  [PHONE_JACK_JBB0819100002]
JP2  JP2  [SIP2]  (value not drawn)
JP3  JP2  [SIP2]  (value not drawn)
R51  10K  [0402R]
R71  10K  [0402R]
R77  20  [0402R]
R78  20  [0402R]
R87  10K  [0402R]
R88  0  [0402R]
R94  [NA]  [0402R]
R95  0  [0402R]
R100  0  [0402R]
R101  210  [0402R]
R102  110  [0402R]
R111  75  [0402R]
R112  1M  [0402R]
R114  [NA]  [0402R]
R115  1M  [0402R]
R116  100  [0402R]
R117  100  [0402R]
TP5  TP  [TP_C40]  (value not drawn)
TP20  Test point 1 pin with hole  [TP]  (value not drawn)
TP103  TP  [TP_C40]  (value not drawn)
TP104  TP  [TP_C40]  (value not drawn)
TP105  TP  [TP_C40]  (value not drawn)
TP106  TP  [TP_C40]  (value not drawn)
TP107  TP  [TP_C40]  (value not drawn)
TP108  TP  [TP_C40]  (value not drawn)
TP109  TP  [TP_C40]  (value not drawn)
U5  IMP34DT05TR  [MIC_HCLGA_3X4X1_4LD]
U6  IMP34DT05TR  [MIC_HCLGA_3X4X1_4LD]
U8  IMP34DT05TR  [MIC_HCLGA_3X4X1_4LD]
U9  IMP34DT05TR  [MIC_HCLGA_3X4X1_4LD]
U11  WM8994ECS/R  [BGA72_0R5_4R5X4]
U15  74LVC1G04SE  [SOT-353]
U16  74LVC1G04SE  [SOT-353]

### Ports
Audio_INT, AUDIO_SCL, AUDIO_SDA, DFSDM_CKOUT, DFSDM_DATIN1, DFSDM_DATIN5, SAI1_FSA, SAI1_MCLKA, SAI1_SCKA, SAI1_SDA, SAI1_SDB, SPDIF_RX, SPDIF_TX

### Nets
1V8: C64.1 C91.1 C94.1 U11.D1(LDO2VDD) U11.D8(AVDD2) U11.G9(CPVDD)
3V3: C44.1 C45.1 C55.1 C56.1 C65.1 C67.2 C71.1 C92.1 C117.2 C118.2 R51.2 R71.2 R87.2 R94.2 U5.1(VDD) U6.1(VDD) U8.1(VDD) U9.1(VDD) U11.B2(SPKVDD1) U11.C2(SPKVDD2) U11.D2(DBVDD) U11.E9(LDO1VDD) U15.5(VCC) U16.5(VCC)
GND: C44.2 C45.2 C55.2 C56.2 C63.1 C64.2 C65.2 C67.1 C71.2 C73.1 C74.2 C78.2 C79.1 C90.2 C91.2 C92.2 C93.2 C94.2 C95.1 C117.1 C118.1 CN6.2 CN6.3 CN7.2 CN7.3 CN8.1(Ground) CN8.2(Ground) CN8.3(Ground) CN12.1(Ground) CN12.2(Ground) CN12.3(Ground) R77.2 R78.2 R102.2 R111.1 U5.2(LR) U5.5(GND) U6.5(GND) U8.2(LR) U8.5(GND) U9.5(GND) U11.A1(SPKGND1) U11.A3(SPKMODE) U11.A4(CIFMODE) U11.A5(REFGND) U11.C1(SPKGND2) U11.D6(AGND) U11.E2(DGND) U11.E7(AGND) U11.E8(AGND) U11.F7(HP2GND) U11.G5(HPOUT1FB) U11.H9(CPGND) U15.3(GND) U16.3(GND)  [project net POE7]
Audio_INT: U11.G3(ADCLRCLK1/GPIO1) ; port Audio_INT
AUDIO_SCL: R88.1 ; port AUDIO_SCL
AUDIO_SDA: R95.1 ; port AUDIO_SDA
DFSDM_CKOUT: TP5.1 U5.3(CLK) U6.3(CLK) U8.3(CLK) U9.3(CLK) ; port DFSDM_CKOUT
DFSDM_DATIN1: TP103.1 U5.4(DOUT) U6.4(DOUT) ; port DFSDM_DATIN1
DFSDM_DATIN5: TP104.1 U8.4(DOUT) U9.4(DOUT) ; port DFSDM_DATIN5
MIC_CLK: TP105.1 U11.C6(DMICCLK)
MIC_DATA1: TP106.1 U11.B9(IN2LN/DMICDAT1)
MIC_DATA2: TP107.1 U11.A9(IN2RN/DMICDAT2)
MIC_VDD1: C79.2 TP108.1 U11.A7(MICBIAS1)
MIC_VDD2: C73.2 TP109.1 U11.B6(MICBIAS2)
PD11: R100.1 TP20.1(COMMON) ; port SPDIF_TX
PE3: U11.F2(ADCDAT1) ; port SAI1_SDB
PE4: U11.E3(LRCLK1) ; port SAI1_FSA
PE5: U11.G1(BCLK1) ; port SAI1_SCKA
PE6: U11.E4(DACDAT1) ; port SAI1_SDA
PG7: U11.D3(MCLK1) ; port SAI1_MCLKA
PG12: R112.2 R114.2 U15.4(Y) ; port SPDIF_RX
NetC57_1: C57.1 CN7.4 U11.G6(HPOUT1R)
NetC57_2: C57.2 R78.1
NetC58_1: C58.1 U11.B7(IN1RN)
NetC58_2: C58.2 CN6.4
NetC59_1: C59.1 CN7.6 U11.H6(HPOUT1L)
NetC59_2: C59.2 R77.1
NetC62_1: C62.1 U11.D7(IN1LN)
NetC62_2: C62.2 CN6.6
NetC63_2: C63.2 U11.F1(DCVDD)
NetC74_1: C74.1 U11.G7(CPVOUTP)
NetC78_1: C78.1 U11.H7(CPVOUTN)
NetC82_1: C82.1 U11.H8(CPCB)
NetC82_2: C82.2 U11.G8(CPCA)
NetC87_1: C87.1 R101.2 R102.1
NetC87_2: C87.2 CN8.4(Signal)
NetC90_1: C90.1 U11.E6(VREFC)
NetC93_1: C93.1 U11.D9(AVDD1)
NetC95_2: C95.2 U11.C9(VMIDC)
NetC119_1: C119.1 R114.1 R115.2 U16.4(Y)
NetC119_2: C119.2 R117.1
NetC120_1: C120.1 CN12.4(Signal) R111.2
NetC120_2: C120.2 R116.1
NetJP2_1: JP2.1(COMMON) U11.B1(SPKOUTLN)
NetJP2_2: JP2.2(NO) U11.A2(SPKOUTLP)
NetJP3_1: JP3.1(COMMON) U11.C3(SPKOUTRN)
NetJP3_2: JP3.2(NO) U11.B3(SPKOUTRP)
NetR51_1: R51.1 U6.2(LR)
NetR71_1: R71.1 U9.2(LR)
NetR87_1: R87.1 U11.D4(LDO1ENA) U11.D5(LDO2ENA)
NetR88_2: R88.2 U11.H1(SCLK)
NetR94_1: R94.1 U11.G2(~{CS}/ADDR)
NetR95_2: R95.2 U11.F3(SDA)
NetR100_2: R100.2 R101.1
NetR112_1: R112.1 R117.2 U15.2(A)
NetR115_1: R115.1 R116.2 U16.2(A)

Not connected (* = marked no-connect by the designer): U11 A6(LINEOUTFB)* A8(IN2RP/VRXP)* B4(LINEOUT2P)* B5(LINEOUT1P)* B8(IN2LP/VRXN)* C4(LINEOUT2N)* C5(LINEOUT1N)* C7(IN1RP)* C8(IN1LP)* E1(GPIO2/MCLK2)* E5(GPIO7/ADCDAT2)* F4(GPIO4/LRCLK2)* F5(GPIO9/ADCDAT3)* F6(GPIO11/BCLK3)* F8(HPOUT2P)* F9(HPOUT2N)* G4(GPIO6/ADCLRCLK2)* H2(GPIO3/BCLK2)* H3(GPIO5/DACDAT2)* H4(GPIO8/DACDAT3)* H5(GPIO10/LRCLK3)*; U15 1(NC); U16 1(NC)

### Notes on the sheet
- WM8994 I2C Address : 0011 0100
- Top Right
- (near CN7) Jack Line output Green
- (near U5) Top Left
- Right
- Jack Line input blue
- Left
- Bottom Right
- (near U8) Bottom Left
- SPK Left
- SPK Right
- RCA White for SPDIF input
- First Stage
- Second Stage
- RCA Yellow for SPDIF ouput
- Very close to Output pin 4
- of first stage

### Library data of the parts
C44 C45 C55-C57 C59 C64 C65 C71 C87 C91 C117 C118 = Cap_100nF_X7R_10%_0402: as C42 on sheet ST_LINK_V2-1
C58 C62 C63 C67 C90 = Cap_1uF_X5R_10%_0603: as C41 on sheet ST_LINK_V2-1
C73 C79 C92-C95 = Cap_4.7uF_X5R_10%_0603: Capacitor,4.7uF,16V, X5R,10%,0603,YAGEO; Manuf_Part_1: CC0603KRX5R7BB475; Order: CC0603KRX5R7BB105
C74 C78 C82 = Cap_2.2uF_X5R_10%_0603: Capacitor,2.2uF,10V, X5R,10%,0603,YAGEO; Manuf_Part_1: CC0603KRX5R6BB225; Manuf_Part_2: C0603C225K8PACTU; Manuf_2: KEMET
C119 C120 = Cap_22nF_X7R_10%_0402: Capacitor,22nF,16V,X7R,10%,0402,YAGEO; Manuf_Part_1: CC0402KRX7R7BB223
CN6 = PJ3028B-3_BE: Connector Jack Stereo 3.5mm, female SMT, Blue (Line input); Manuf_Part_2: PJ30280-3_BE
CN7 = PJ3028B-3_GR: Connector Jack Stereo 3.5mm, female SMT, Green (Line output); Manuf_Part_2: PJ30280-3_GR
CN8 = RCA_SMD_Y: RCA Phono Jack, Right Angle, SMD, Yellow; Manuf_Part_1: JBB0819100002; Manuf_1: JIUBABA; Manuf_2: CUI Inc; Manuf_Part_2: RCJ-014-SMT
CN12 = RCA_SMD_W: RCA Phono Jack, Right Angle, SMD, White; Manuf_Part_1: JBB0819100004; Manuf_1: JIUBABA; Manuf_2: CUI Inc; Manuf_Part_2: RCJ-013-SMT
JP2 JP3 = JP2: Fitted: NO
R51 R71 R87 = Res_10K_1%_0402: as R122 on sheet ST_LINK_V2-1
R77 R78 = Res_20_1%_0402: Resistor,20,0402,1%,YAGEO; Manuf_Part_1: RC0402FR-0720RL
R88 R95 R100 = Res_0_5%_0402: Resistor,0,0402,5%,YAGEO; Manuf_Part_1: RC0402JR-070RL; Order: 2363467
R94 R114 = Res_NA_0402: Resistor,[NA],0402; Fitted: NO
R101 = Res_210_1%_0402: Resistor,210,0402,1%,YAGEO; Manuf_Part_1: RC0402FR-07210RL
R102 = Res_110_1%_0402: Resistor,110,0402,1%,YAGEO; Manuf_Part_1: RC0402FR-07110RL
R111 = Res_75_1%_0402: Resistor,75,0402,1%,YAGEO; Manuf_Part_1: RC0402FR-0775RL; Order: 311-75.0LRTR-ND
R112 R115 = Res_1M_1%_0402: Resistor,1M,0402,1%,YAGEO; Manuf_Part_1: RC0402FR-071ML
R116 R117 = Res_100_1%_0402: as R143 on sheet ST_LINK_V2-1
TP5 TP103-TP109 = TP: Test Point
TP20 = TP1: Test Point; Fitted: NO
U5 U6 U8 U9 = MCD-01715: MEMS audio sensor omnidirectional digital microphone for industrial applications; BMS_Part_Number: 9177995; Part_Type: IC; Part_Preference: Recommended; Manufacturer: STMICROELECTRONICS; Manufacturer_HQ_COO: EU; Component_Country_Of_Origin: Philippines
U11 = WM8994ECS/R: Multi-Channel Audio Hub CODEC for Smartphones; Manuf_1: Cirrus Logic; ECCN_US/EU: EAR99/NEC
U15 U16 = 74LVC1G04SE: Single inverter gate with a standard push-pull output. (1.65V to 5.5V); Manuf_Part_1: 74LVC1G04SE-7; Manuf_1: DIODES; Order: 1845218; ECCN_US/EU: EAR99/NEC

## Sheet Peripherals.SchDoc: uSD, Wifi, LEDs and Push Button
size A4; Date: 29-OCT-2015; Author: A.B; CompanyName: STMicroelectronics; Organization: MCD/TOOLS/GNB; Address1: 12, Rue Jules HOROWITZ; Address2: 38019 Grenoble; Address3: FRANCE; DocumentNumber: MB1225; Revision: B-01; SheetNumber: 13; SheetTotal: 13; Project: STM32F769I-DISCO
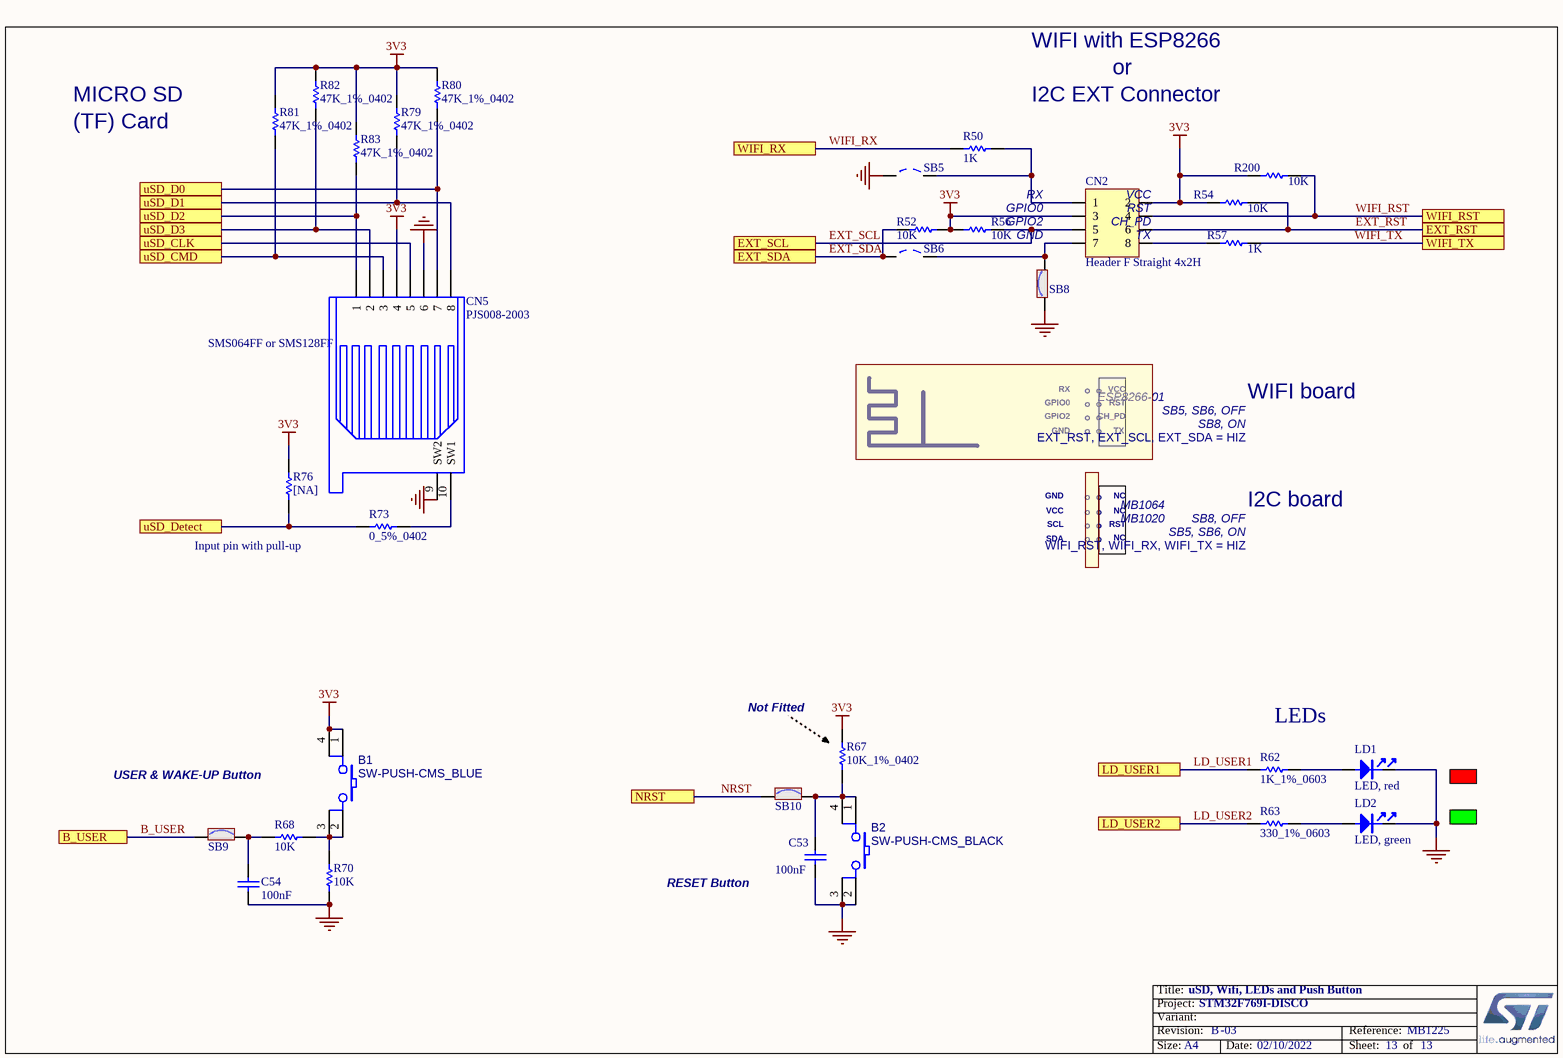
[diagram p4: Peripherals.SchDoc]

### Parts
B1  SW-PUSH-CMS_BLUE  [PB10]
B2  SW-PUSH-CMS_BLACK  [PB10]
C53  100nF  [0402C]
C54  100nF  [0402C]
CN2  Header F Straight 4x2H  [HDR_2X4_2R54]
CN5  PJS008-2003  [MSD_PJS008_]
LD1  LED, red  [0603D]
LD2  LED, green  [0603D]
R50  1K  [0402R]
R52  10K  [0402R]
R54  10K  [0402R]
R56  10K  [0402R]
R57  1K  [0402R]
R62  1K_1%_0603  [0603R]
R63  330_1%_0603  [0603R]
R67  10K_1%_0402  [0402R]
R68  10K  [0402R]
R70  10K  [0402R]
R73  0_5%_0402  [0402R]
R76  [NA]  [0402R]
R79  47K_1%_0402  [0402R]
R80  47K_1%_0402  [0402R]
R81  47K_1%_0402  [0402R]
R82  47K_1%_0402  [0402R]
R83  47K_1%_0402  [0402R]
R200  10K  [0402R]
SB5  Solder Bridge OFF  [JP2_SMD]  (value not drawn)
SB6  Solder Bridge OFF  [JP2_SMD]  (value not drawn)
SB8  Solder Bridge ON  [JP2_SMD]  (value not drawn)
SB9  Solder Bridge ON  [JP2_SMD]  (value not drawn)
SB10  Solder Bridge ON  [JP2_SMD]  (value not drawn)

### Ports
B_USER, EXT_RST, EXT_SCL, EXT_SDA, LD_USER1, LD_USER2, NRST, uSD_CLK, uSD_CMD, uSD_D0, uSD_D1, uSD_D2, uSD_D3, uSD_Detect, WIFI_RST, WIFI_RX, WIFI_TX

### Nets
3V3: B1.1 B1.4 CN2.2 CN2.3 CN5.4 R52.2 R54.1 R56.1 R67.2 R76.2 R79.2 R80.2 R81.2 R82.2 R83.2 R200.1
GND: B2.2 B2.3 C53.1 C54.1 CN5.6 CN5.9(SW2) LD1.2 LD2.2 R70.1 SB5.1 SB8.1  [project net POE7]
B_USER: SB9.1 ; port B_USER
EXT_RST: CN2.6 R54.2 ; port EXT_RST
EXT_SCL: CN2.5 R56.2 ; port EXT_SCL
EXT_SDA: R52.1 SB6.1 ; port EXT_SDA
LD_USER1: R62.1 ; port LD_USER1
LD_USER2: R63.1 ; port LD_USER2
NRST: SB10.1 ; port NRST
PB4: CN5.2 R82.1 ; port uSD_D3
PD6: CN5.5 ; port uSD_CLK
PD7: CN5.3 R81.1 ; port uSD_CMD
PG9: CN5.7 R80.1 ; port uSD_D0
PG10: CN5.8 R79.1 ; port uSD_D1
PI15: R73.1 R76.1 ; port uSD_Detect
uSD_D2: CN5.1 R83.1 ; port uSD_D2
WIFI_RST: CN2.4 R200.2 ; port WIFI_RST  [project net PJ14]
WIFI_RX: R50.1 ; port WIFI_RX  [project net PC12]
WIFI_TX: R57.2 ; port WIFI_TX  [project net PD2]
NetB1_2: B1.2 B1.3 R68.2 R70.2
NetB2_1: B2.1 B2.4 C53.2 R67.1 SB10.2
NetC54_2: C54.2 R68.1 SB9.2
NetCN2_1: CN2.1 R50.2 SB5.2
NetCN2_7: CN2.7 SB6.2 SB8.2
NetCN2_8: CN2.8 R57.1
NetCN5_10: CN5.10(SW1) R73.2
NetLD1_1: LD1.1 R62.2
NetLD2_1: LD2.1 R63.2

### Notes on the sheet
- WIFI with ESP8266
- MICRO SD
- (TF) Card
- I2C EXT Connector
- or
- (near CN2) RX
- (near CN2) VCC
- GND
- (near CN2) GPIO2
- (near CN2) GPIO0
- (near CN2) CH_PD
- (near CN2) RST
- (near CN2) TX
- (near CN5) SMS064FF or SMS128FF
- GPIO0
- RX
- ° °
- VCC
- RST
- ESP8266-01
- WIFI board
- GPIO2
- TX
- CH_PD
- SB5, SB6, OFF
- SB8, ON
- EXT_RST, EXT_SCL, EXT_SDA = HIZ
- SCL
- SDA
- NC
- MB1064
- MB1020
- I2C board
- SB8, OFF
- SB5, SB6, ON
- Input pin with pull-up
- WIFI_RST, WIFI_RX, WIFI_TX = HIZ
- (near R67) Not Fitted
- LEDs
- USER & WAKE-UP Button
- RESET Button

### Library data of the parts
B1 = SW-PUSH-CMS_BLUE: Non-Open Push-Button 0.1A 24V; Manuf_2: FARNELL; Manuf_Part_2: 535-930; Manuf_1: wealthmetal; Manuf_Part_1: TD0341X-G01-BLU; Ref St: 9180120; SMEE_FP: BP1CMS; Provided: Sub Co
B2 = SW-PUSH-CMS_BLACK: Non-Open Push-Button 0.1A 24V; Manuf_2: FARNELL; Manuf_Part_2: 535-930; Manuf_1: wealthmetal; Manuf_Part_1: TD0341X-G01-BLA; Ref St: 9180120; SMEE_FP: BP1CMS; SOFER_FP: BP10; Provided: Sub Co
C53 C54 = Cap_100nF_X7R_10%_0402: as C42 on sheet ST_LINK_V2-1
CN2 = Header 4X2F: Header Female, 4-Pin, Dual row, Straight; Manuf_Part_1: BL 2-8G; Manuf_1: Fischer Electronik
CN5 = microSD-PJS008-2003: Memory Card Connectors MicroSD Card Conn Revrs Mnt Push-Push; Manuf_Part_1: PJS008-2003-1; Manuf_1: YAMAICHI
LD1 = LED_red: as LD6 on sheet ST_LINK_V2-1
LD2 = LED_green: LED, green, 0603; Manuf_1: everlight; Manuf_Part_1: 19-213SYGC/S530-E2/TR8; ECCN_US/EU: EAR99/NEC
R50 R57 = Res_1K_1%_0402: as R58 on sheet ST_LINK_V2-1
R52 R54 R56 R68 R70 R200 = Res_10K_1%_0402: as R122 on sheet ST_LINK_V2-1
R62 = Res_1K_1%_0603: Resistor,1K,0603,1%,YAGEO; Manuf_Part_1: RC0603FR-071KL
R63 = Res_330_1%_0603: Resistor,330,0603,1%,YAGEO; Manuf_Part_1: RC0603FR-07330RL; Manuf_Part_2: RT0603FRE07330RL; Value: 330
R67 = Res_10K_1%_0402: Resistor,10K,0402,1%,YAGEO; Manuf_Part_1: RC0402FR-0710KL; Fitted: NO
R73 = Res_0_5%_0402: Resistor,0,0402,5%,YAGEO; Manuf_Part_1: RC0402JR-070RL; Value: 0; Order: 2363467
R76 = Res_NA_0402: Resistor,[NA],0402; Fitted: NO
R79-R83 = Res_47K_1%_0402: Resistor,47K,0402,1%,YAGEO; Manuf_Part_1: RC0402FR-0747KL; Order: 9239430
SB5 SB6 = SB_OFF: Solder: NO
SB8-SB10 = SB_ON: Solder: YES

## Sheet QSPI.SchDoc: Quad SPI Flash Memory (MICRON)
size A4; Date: 29-OCT-2015; Author: A.B; CompanyName: STMicroelectronics; Organization: MCD/TOOLS/GNB; Address1: 12, Rue Jules HOROWITZ; Address2: 38019 Grenoble; Address3: FRANCE; DocumentNumber: MB1225; Revision: B-01; SheetNumber: 7; SheetTotal: 13; Project: STM32F769I-DISCO
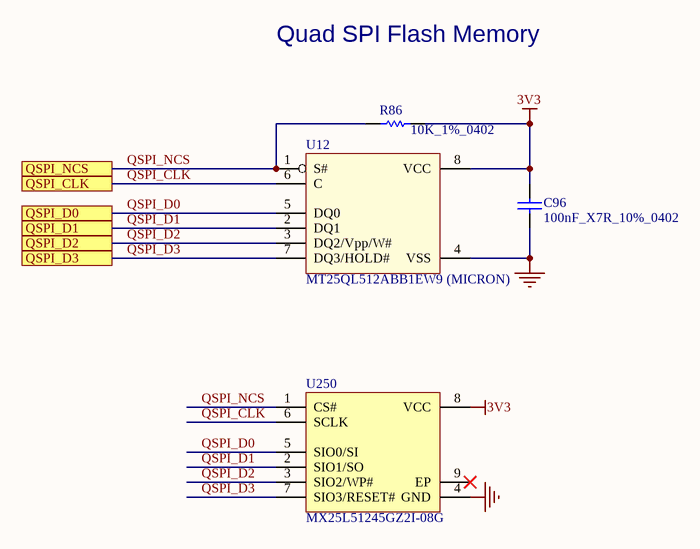
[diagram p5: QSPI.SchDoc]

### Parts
C96  100nF_X7R_10%_0402  [0402C]
R86  10K_1%_0402  [0402R]
U12  MT25QL512ABB1EW9 (MICRON)  [DFN8_1R27_6X8_TP4R8X5R16]
U250  MX25L51245GZ2I-08G  [ICC_WSON8-EPAD_8X6_P127]

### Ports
QSPI_CLK, QSPI_D0, QSPI_D1, QSPI_D2, QSPI_D3, QSPI_NCS

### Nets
3V3: C96.2 R86.2 U12.8(VCC) U250.8(VCC)
GND: C96.1 U12.4(VSS) U250.4(GND)  [project net POE7]
QSPI_CLK: U12.6(C) U250.6(SCLK) ; port QSPI_CLK  [project net PB2]
QSPI_D0: U12.5(DQ0) U250.5(SIO0/SI) ; port QSPI_D0  [project net PC9]
QSPI_D1: U12.2(DQ1) U250.2(SIO1/SO) ; port QSPI_D1  [project net PC10]
QSPI_D2: U12.3(DQ2/Vpp/W#) U250.3(SIO2/WP#) ; port QSPI_D2  [project net PE2]
QSPI_D3: U12.7(DQ3/HOLD#) U250.7(SIO3/RESET#) ; port QSPI_D3  [project net PD13]
QSPI_NCS: R86.1 U12.1(S#) U250.1(CS#) ; port QSPI_NCS  [project net PB6]

Not connected (* = marked no-connect by the designer): U250 9(EP)*

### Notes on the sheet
- Quad SPI Flash Memory

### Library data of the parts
C96 = Cap_100nF_X7R_10%_0402: as C42 on sheet ST_LINK_V2-1
R86 = Res_10K_1%_0402: as R122 on sheet ST_LINK_V2-1
U12 = MT25QL512ABB1EW9: 512Mb, 3V, Multiple I/O Serial Flash Memory, Quad/Dual; Manuf_Part_2: N25Q512A13GF840E; Manuf_Part_1: MT25QL512ABB1EW9-0SIT; ECCN_US/EU: 3A991/NEC; Provided: ST; Ref St: xxxxxxxx; Note: MX25L51245GZ2I-08G can also be use but with a different footprint; Fitted: NO
U250 = MCD-01077: 3V 512M-BIT CMOS MXSMIO FLASH MEMORY; Part_Type: IC; Part_Preference: Recommended; Manufacturer: MACRONIX; Component_Country_Of_Origin: Unknown

## Sheet Arduino_ Connectors.SchDoc: Arduino UNO connectors
size A4; Date: 29-OCT-2015; Author: A.B; CompanyName: STMicroelectronics; Organization: MCD/TOOLS/GNB; Address1: 12, Rue Jules HOROWITZ; Address2: 38019 Grenoble; Address3: FRANCE; DocumentNumber: MB1225; Revision: B-01; SheetNumber: 8; SheetTotal: 13; Project: STM32F769I-DISCO
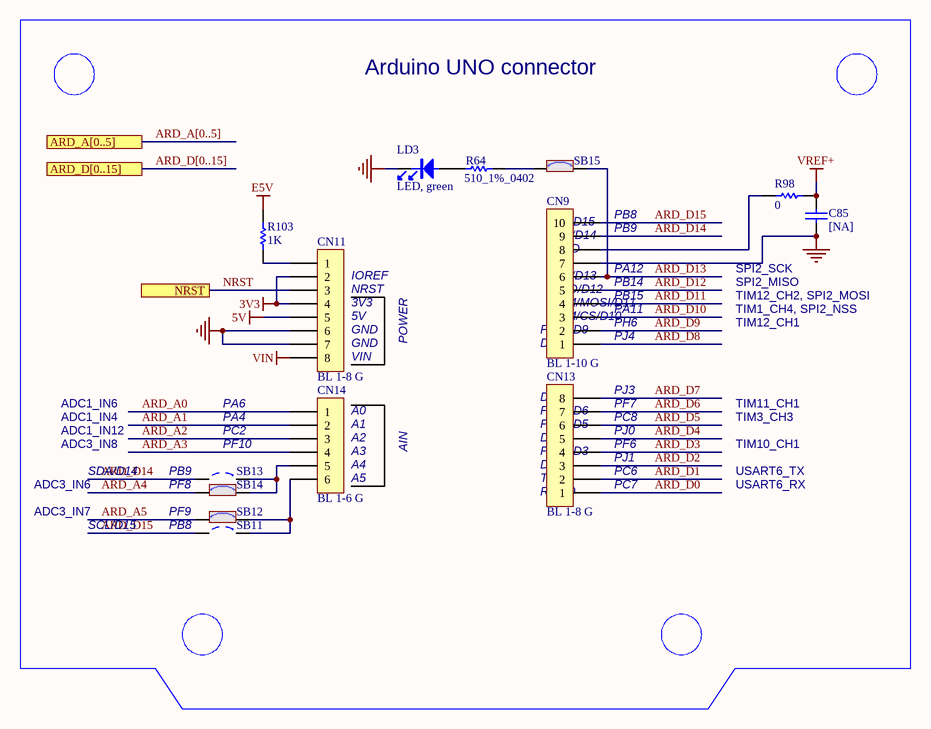
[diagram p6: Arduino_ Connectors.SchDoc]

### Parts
C85  [NA]  [0402C]
CN9  BL 1-10 G  [HDR_1X10_2R54_W]
CN11  BL 1-8 G  [HDR_1X8_2R54_W]
CN13  BL 1-8 G  [HDR_1X8_2R54_W]
CN14  BL 1-6 G  [HDR_1X6_2R54_W]
LD3  LED, green  [0603D]
R64  510_1%_0402  [0402R]
R98  0  [0402R]
R103  1K  [0402R]
SB11  Solder Bridge OFF  [JP2_SMD]  (value not drawn)
SB12  Solder Bridge ON  [JP2_SMD]  (value not drawn)
SB13  Solder Bridge OFF  [JP2_SMD]  (value not drawn)
SB14  Solder Bridge ON  [JP2_SMD]  (value not drawn)
SB15  Solder Bridge ON  [JP2_SMD]  (value not drawn)

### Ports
ARD_A[0..5], ARD_D[0..15], NRST

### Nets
3V3: CN11.2 CN11.4
5V: CN11.5
E5V: R103.2
GND: C85.1 CN9.7 CN11.6 CN11.7 LD3.2  [project net POE7]
VIN: CN11.8
VREF+: C85.2 R98.2
ARD_A0: CN14.1
ARD_A1: CN14.2
ARD_A2: CN14.3
ARD_A3: CN14.4
ARD_A4: SB14.1
ARD_A5: SB12.1
ARD_D0: CN13.1
ARD_D1: CN13.2
ARD_D2: CN13.3
ARD_D3: CN13.4
ARD_D4: CN13.5
ARD_D5: CN13.6
ARD_D6: CN13.7
ARD_D7: CN13.8
ARD_D8: CN9.1
ARD_D9: CN9.2
ARD_D10: CN9.3
ARD_D11: CN9.4
ARD_D12: CN9.5
ARD_D13: CN9.6 SB15.2
ARD_D14: CN9.9 SB13.1
ARD_D15: CN9.10 SB11.1
NRST: CN11.3 ; port NRST
NetCN9_8: CN9.8 R98.1
NetCN11_1: CN11.1 R103.1
NetCN14_5: CN14.5 SB13.2 SB14.2
NetCN14_6: CN14.6 SB11.2 SB12.2
NetLD3_1: LD3.1 R64.1
NetR64_2: R64.2 SB15.1

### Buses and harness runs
bus ARD_A[0..5] = port ARD_A[0..5]
bus ARD_D[0..15] = port ARD_D[0..15]

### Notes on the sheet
- Arduino UNO connector
- PB8
- (near CN11) IOREF
- (near CN11) NRST
- (near CN9) SDA/D14
- (near CN9) SCL/D15
- (near CN9) SCK/D13
- (near CN9) MISO/D12
- (near CN9) AVDD
- (near CN9) GND
- (near CN9) PB14
- (near CN9) PA12
- (near CN9) PB9
- SPI2_MISO
- SPI2_SCK
- (near CN11) 3V3
- (near CN11) 5V
- (near CN11) GND
- POWER
- (near CN9) D8
- (near CN9) PWM/D9
- (near CN9) PWM/CS/D10
- (near CN9) PWM/MOSI/D11
- (near CN9) PA11
- (near CN9) PJ4
- (near CN9) PH6
- (near CN9) PB15
- TIM12_CH1
- TIM1_CH4, SPI2_NSS
- TIM12_CH2, SPI2_MOSI
- ADC1_IN4
- ADC1_IN6
- PA6
- PA4
- (near CN14) A0
- (near CN14) A1
- (near CN11) VIN
- (near CN13) PWM/D5
- (near CN13) PWM/D6
- (near CN13) D7
- (near CN13) PF7
- PJ3
- (near CN13) PC8
- TIM3_CH3
- TIM11_CH1
- ADC3_IN6
- ADC3_IN8
- ADC1_IN12
- SDA/D14
- PB9
- PF8
- PC2
- PF10
- (near CN14) A2
- (near CN14) A3
- (near CN14) A4
- (near CN14) A5
- AIN
- (near CN13) TX/D1
- (near CN13) D2
- (near CN13) D4
- (near CN13) PWM/D3
- (near CN13) PC6
- (near CN13) PJ1
- (near CN13) PF6
- (near CN13) PJ0
- (near CN13) PC7
- USART6_RX
- USART6_TX
- TIM10_CH1
- ADC3_IN7
- SCL/D15
- PF9
- (near CN13) RX/D0

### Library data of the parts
C85 = Cap_NA_0402: Capacitor,NA,0402; Fitted: NO
CN9 = Header 10X1_Female_THT: Header, 10-Pin, Single row, female, THT, 2.54; Manuf_1: Fischer Electronik
CN11 CN13 = Header 8X1_Female_THT: Header, 8-Pins, Single row, female, THT, 2.54; Manuf_1: Fischer Electronik
CN14 = Header 6X1_Female_THT: Header, 6-Pins, Single row, female THT, 2.54; Manuf_1: Fischer Electronik
LD3 = LED_green: as LD2 on sheet Peripherals
R64 = Res_510_1%_0402: Resistor,510,0402,1%,YAGEO; Manuf_Part_1: RC0402FR-07510L; Value: 510
R98 = Res_0_5%_0402: as R88 on sheet AUDIO
R103 = Res_1K_1%_0402: as R58 on sheet ST_LINK_V2-1
SB11 SB13 = SB_OFF: Solder: NO
SB12 SB14 SB15 = SB_ON: Solder: YES

## Sheet SDRAM.SchDoc: SDRAM (MICRON)
size A4; Date: 29-OCT-2015; Author: A.B; CompanyName: STMicroelectronics; Organization: MCD/TOOLS/GNB; Address1: 12, Rue Jules HOROWITZ; Address2: 38019 Grenoble; Address3: FRANCE; DocumentNumber: MB1225; Revision: B-01; SheetNumber: 6; SheetTotal: 13; Project: STM32F769I-DISCO
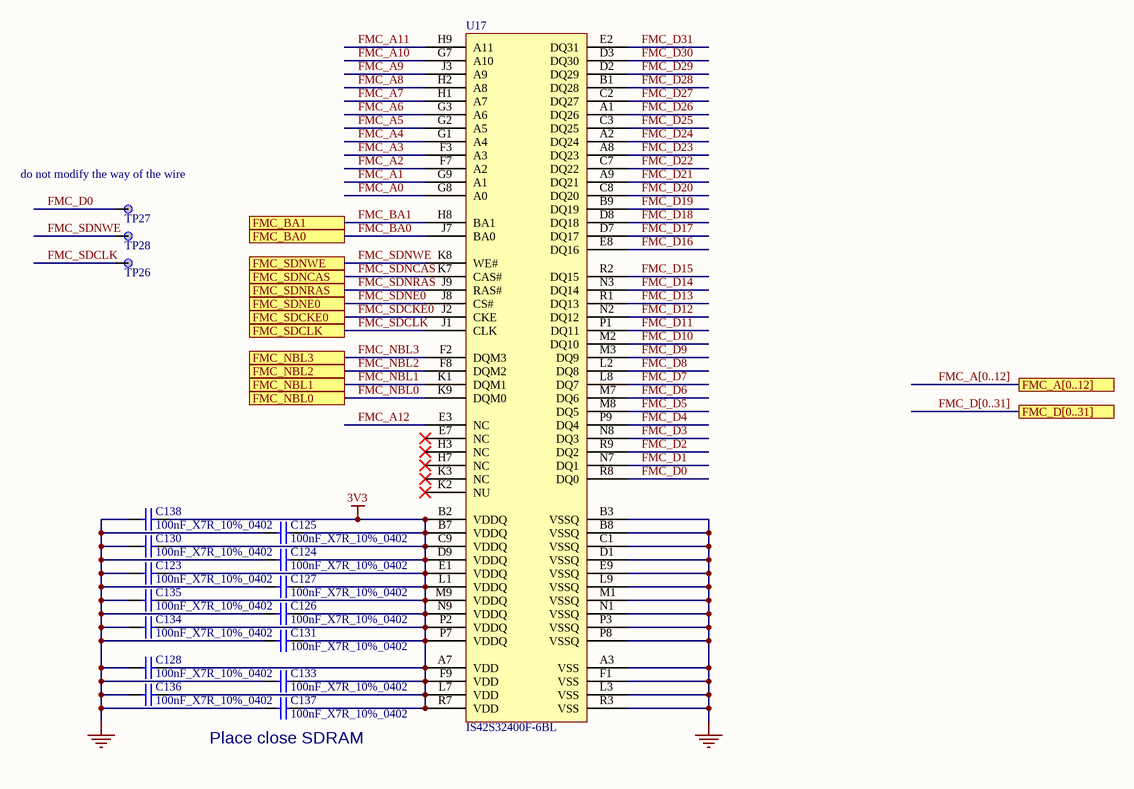
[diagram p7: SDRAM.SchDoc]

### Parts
C123  100nF_X7R_10%_0402  [0402C]
C124  100nF_X7R_10%_0402  [0402C]
C125  100nF_X7R_10%_0402  [0402C]
C126  100nF_X7R_10%_0402  [0402C]
C127  100nF_X7R_10%_0402  [0402C]
C128  100nF_X7R_10%_0402  [0402C]
C130  100nF_X7R_10%_0402  [0402C]
C131  100nF_X7R_10%_0402  [0402C]
C133  100nF_X7R_10%_0402  [0402C]
C134  100nF_X7R_10%_0402  [0402C]
C135  100nF_X7R_10%_0402  [0402C]
C136  100nF_X7R_10%_0402  [0402C]
C137  100nF_X7R_10%_0402  [0402C]
C138  100nF_X7R_10%_0402  [0402C]
TP26  TP  [TP_C40]  (value not drawn)
TP27  TP  [TP_C40]  (value not drawn)
TP28  TP  [TP_C40]  (value not drawn)
U17  IS42S32400F-6BL  [ICC_VFBGA90_8X13_P080]

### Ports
FMC_A[0..12], FMC_BA0, FMC_BA1, FMC_D[0..31], FMC_NBL0, FMC_NBL1, FMC_NBL2, FMC_NBL3, FMC_SDCKE0, FMC_SDCLK, FMC_SDNCAS, FMC_SDNE0, FMC_SDNRAS, FMC_SDNWE

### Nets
3V3: C123.2 C124.2 C125.2 C126.2 C127.2 C128.2 C130.2 C131.2 C133.2 C134.2 C135.2 C136.2 C137.2 C138.2 U17.A7(VDD) U17.B2(VDDQ) U17.B7(VDDQ) U17.C9(VDDQ) U17.D9(VDDQ) U17.E1(VDDQ) U17.F9(VDD) U17.L1(VDDQ) U17.L7(VDD) U17.M9(VDDQ) U17.N9(VDDQ) U17.P2(VDDQ) U17.P7(VDDQ) U17.R7(VDD)
GND: C123.1 C124.1 C125.1 C126.1 C127.1 C128.1 C130.1 C131.1 C133.1 C134.1 C135.1 C136.1 C137.1 C138.1 U17.A3(VSS) U17.B3(VSSQ) U17.B8(VSSQ) U17.C1(VSSQ) U17.D1(VSSQ) U17.E9(VSSQ) U17.F1(VSS) U17.L3(VSS) U17.L9(VSSQ) U17.M1(VSSQ) U17.N1(VSSQ) U17.P3(VSSQ) U17.P8(VSSQ) U17.R3(VSS)  [project net POE7]
FMC_A0: U17.G8(A0)
FMC_A1: U17.G9(A1)
FMC_A2: U17.F7(A2)
FMC_A3: U17.F3(A3)
FMC_A4: U17.G1(A4)
FMC_A5: U17.G2(A5)
FMC_A6: U17.G3(A6)
FMC_A7: U17.H1(A7)
FMC_A8: U17.H2(A8)
FMC_A9: U17.J3(A9)
FMC_A10: U17.G7(A10)
FMC_A11: U17.H9(A11)
FMC_A12: U17.E3(NC)
FMC_BA0: U17.J7(BA0) ; port FMC_BA0
FMC_BA1: U17.H8(BA1) ; port FMC_BA1
FMC_D0: TP27.1 U17.R8(DQ0)
FMC_D1: U17.N7(DQ1)
FMC_D2: U17.R9(DQ2)
FMC_D3: U17.N8(DQ3)
FMC_D4: U17.P9(DQ4)
FMC_D5: U17.M8(DQ5)
FMC_D6: U17.M7(DQ6)
FMC_D7: U17.L8(DQ7)
FMC_D8: U17.L2(DQ8)
FMC_D9: U17.M3(DQ9)
FMC_D10: U17.M2(DQ10)
FMC_D11: U17.P1(DQ11)
FMC_D12: U17.N2(DQ12)
FMC_D13: U17.R1(DQ13)
FMC_D14: U17.N3(DQ14)
FMC_D15: U17.R2(DQ15)
FMC_D16: U17.E8(DQ16)
FMC_D17: U17.D7(DQ17)
FMC_D18: U17.D8(DQ18)
FMC_D19: U17.B9(DQ19)
FMC_D20: U17.C8(DQ20)
FMC_D21: U17.A9(DQ21)
FMC_D22: U17.C7(DQ22)
FMC_D23: U17.A8(DQ23)
FMC_D24: U17.A2(DQ24)
FMC_D25: U17.C3(DQ25)
FMC_D26: U17.A1(DQ26)
FMC_D27: U17.C2(DQ27)
FMC_D28: U17.B1(DQ28)
FMC_D29: U17.D2(DQ29)
FMC_D30: U17.D3(DQ30)
FMC_D31: U17.E2(DQ31)
FMC_NBL0: U17.K9(DQM0) ; port FMC_NBL0
FMC_NBL1: U17.K1(DQM1) ; port FMC_NBL1
FMC_NBL2: U17.F8(DQM2) ; port FMC_NBL2
FMC_NBL3: U17.F2(DQM3) ; port FMC_NBL3
FMC_SDCKE0: U17.J2(CKE) ; port FMC_SDCKE0
FMC_SDCLK: TP26.1 U17.J1(CLK) ; port FMC_SDCLK
FMC_SDNCAS: U17.K7(CAS#) ; port FMC_SDNCAS
FMC_SDNE0: U17.J8(CS#) ; port FMC_SDNE0
FMC_SDNRAS: U17.J9(RAS#) ; port FMC_SDNRAS
FMC_SDNWE: TP28.1 U17.K8(WE#) ; port FMC_SDNWE

Not connected (* = marked no-connect by the designer): U17 E7(NC)* H3(NC)* H7(NC)* K2(NU)* K3(NC)*

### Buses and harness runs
bus FMC_A[0..12] = port FMC_A[0..12]
bus FMC_D[0..31] = port FMC_D[0..31]

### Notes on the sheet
- (near TP27) do not modify the way of the wire
- (near C137) Place close SDRAM

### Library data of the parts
C123-C128 C130 C131 C133-C138 = Cap_100nF_X7R_10%_0402: as C42 on sheet ST_LINK_V2-1
TP26-TP28 = TP: Test Point
U17 = MCD-01977: SDRAM 128MBit 166MHZ 90BGA; Part_Type: IC; Part_Preference: Recommended; Manufacturer: ISSI; Component_Country_Of_Origin: China, Taiwan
